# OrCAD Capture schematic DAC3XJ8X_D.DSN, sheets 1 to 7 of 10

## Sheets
1 SHEET 1 - BLOCK DIAGRAM: title: BLOCK DIAGRAM; rev: D; note: DAC3XJ8X EVM
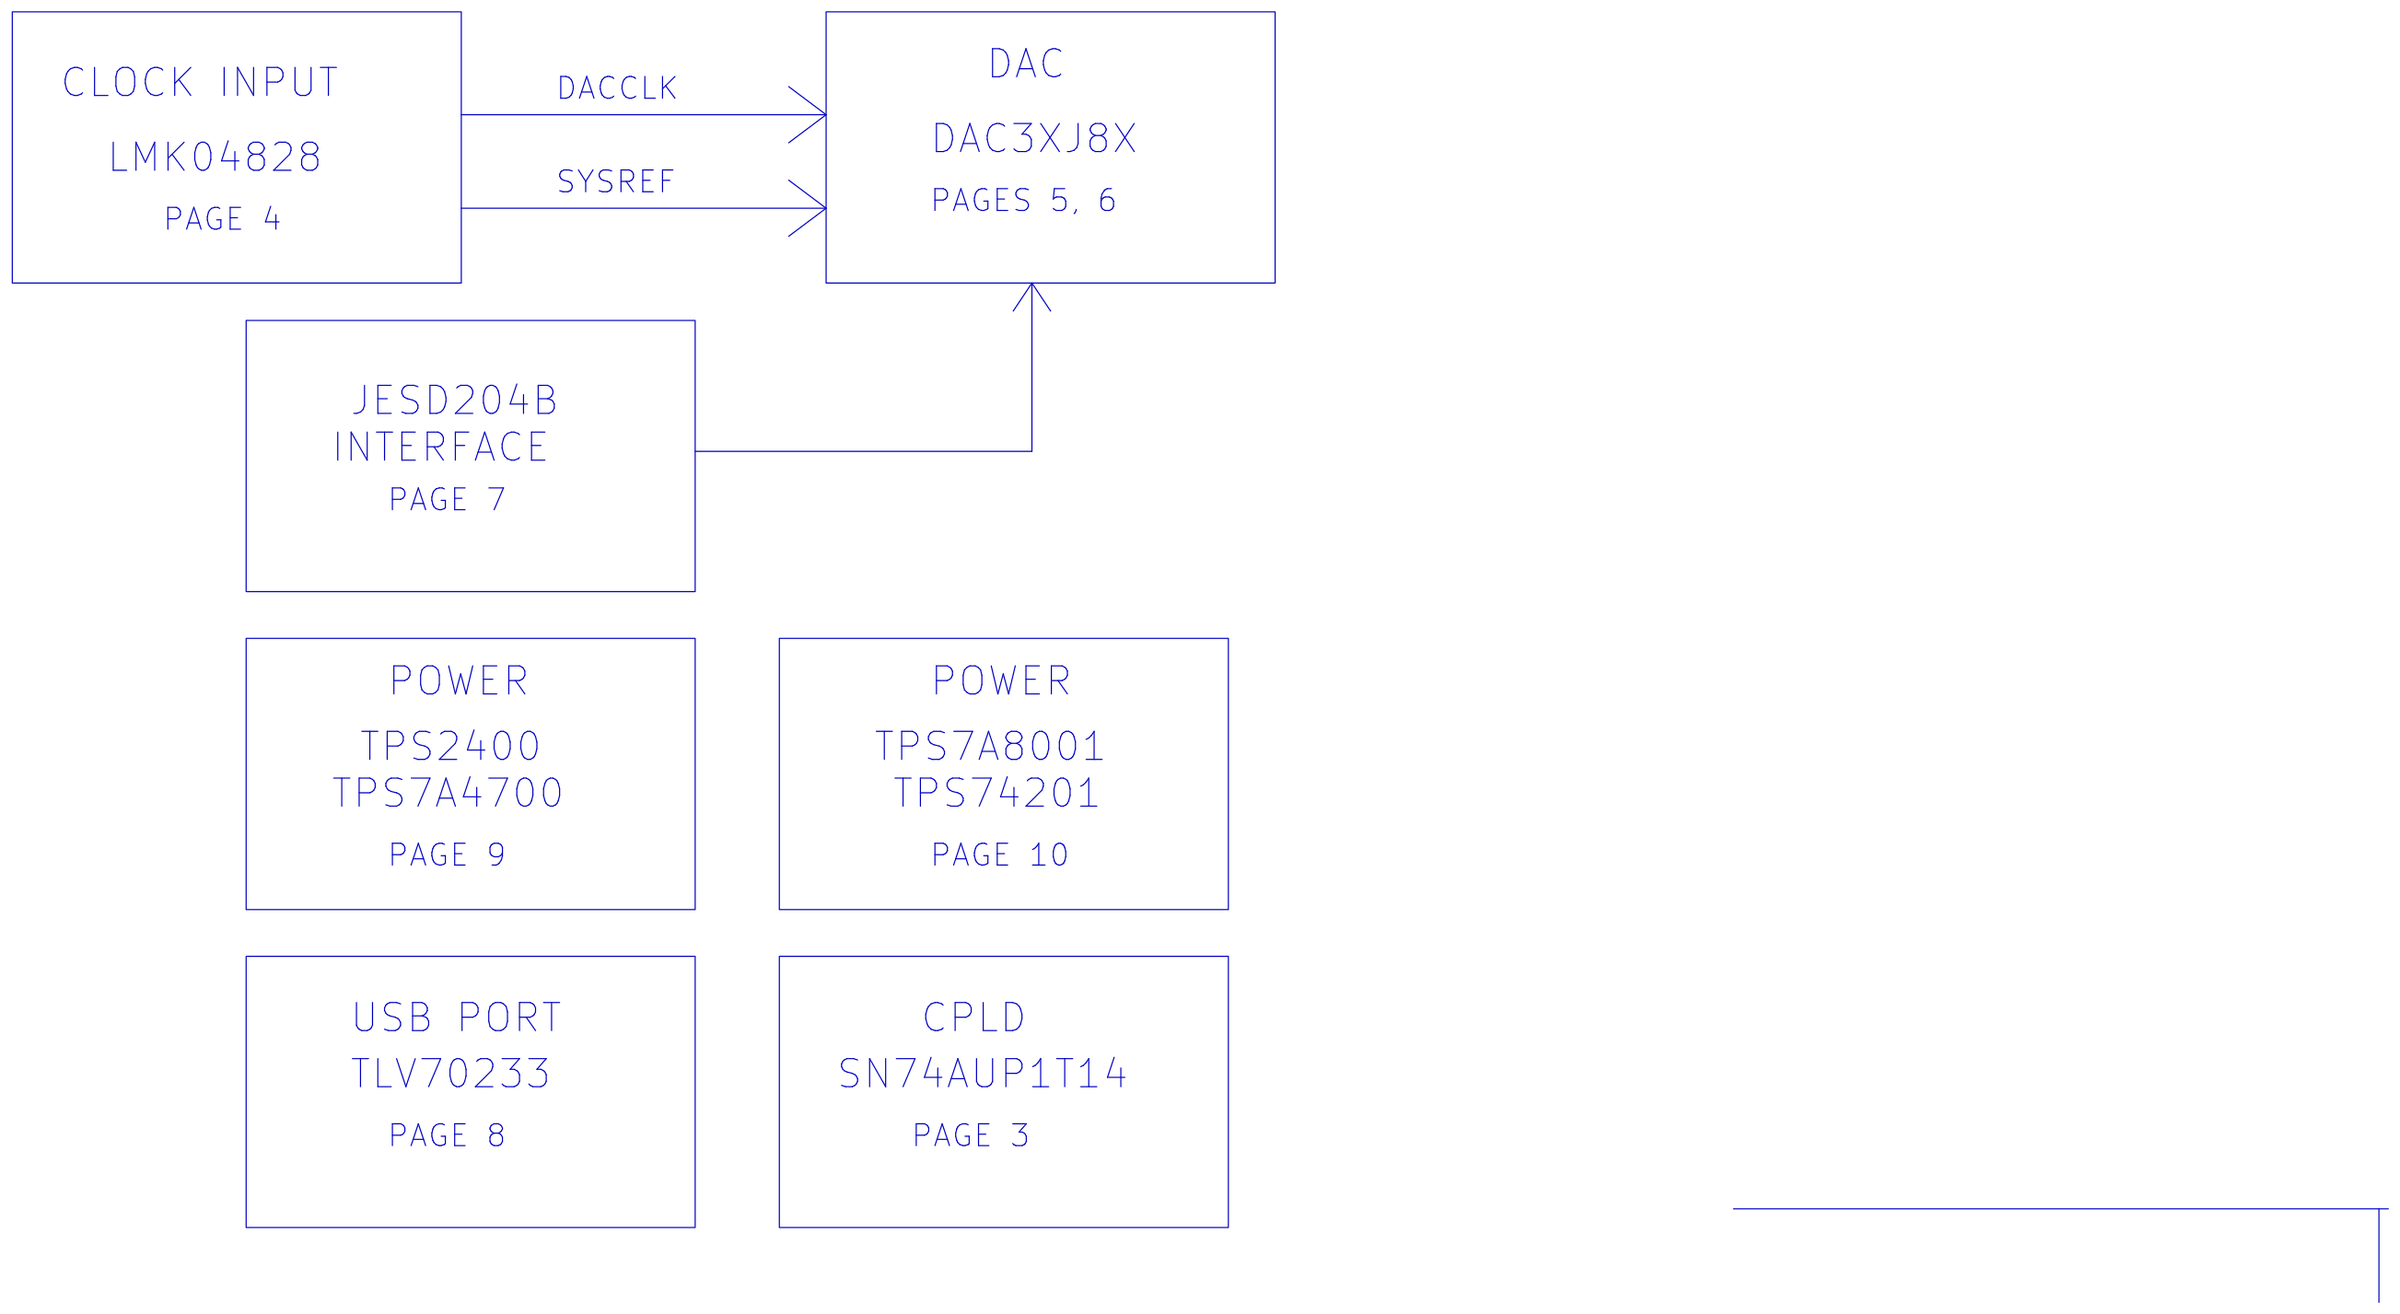
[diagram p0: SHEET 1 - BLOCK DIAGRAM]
2 SHEET 10 - MORE POWER: size B; title: MAIN POWER
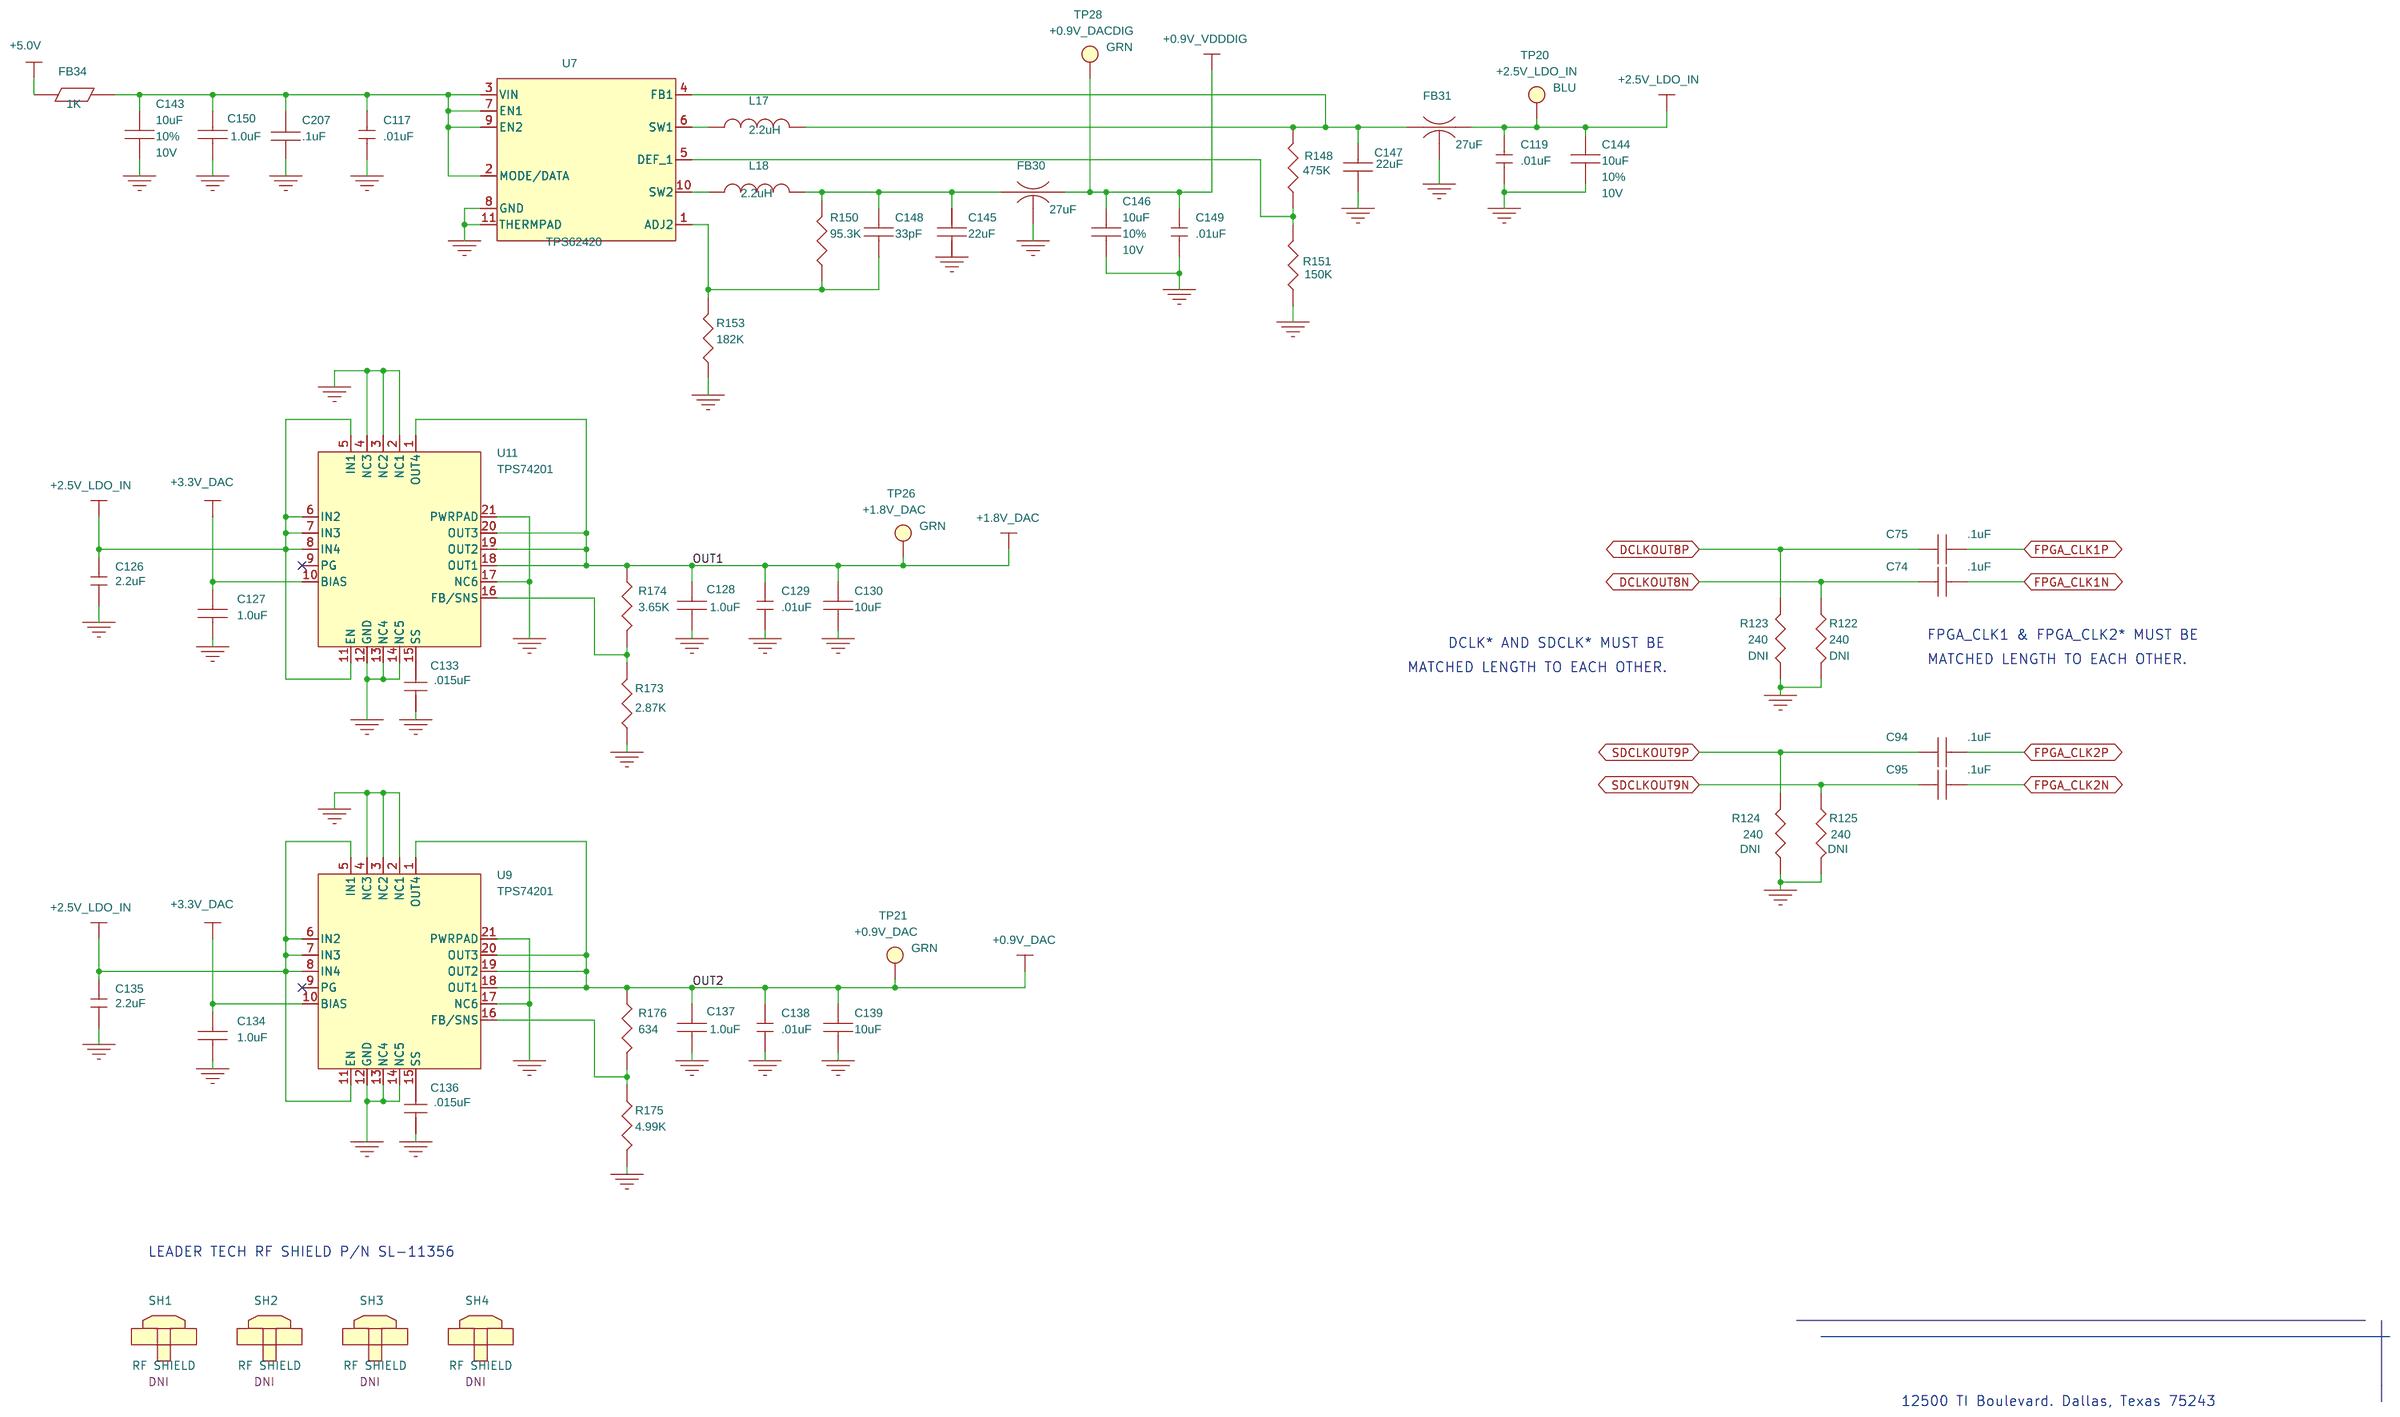
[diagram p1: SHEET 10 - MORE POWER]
3 SHEET 6 - POWER FOR DAC: size B; title: DAC
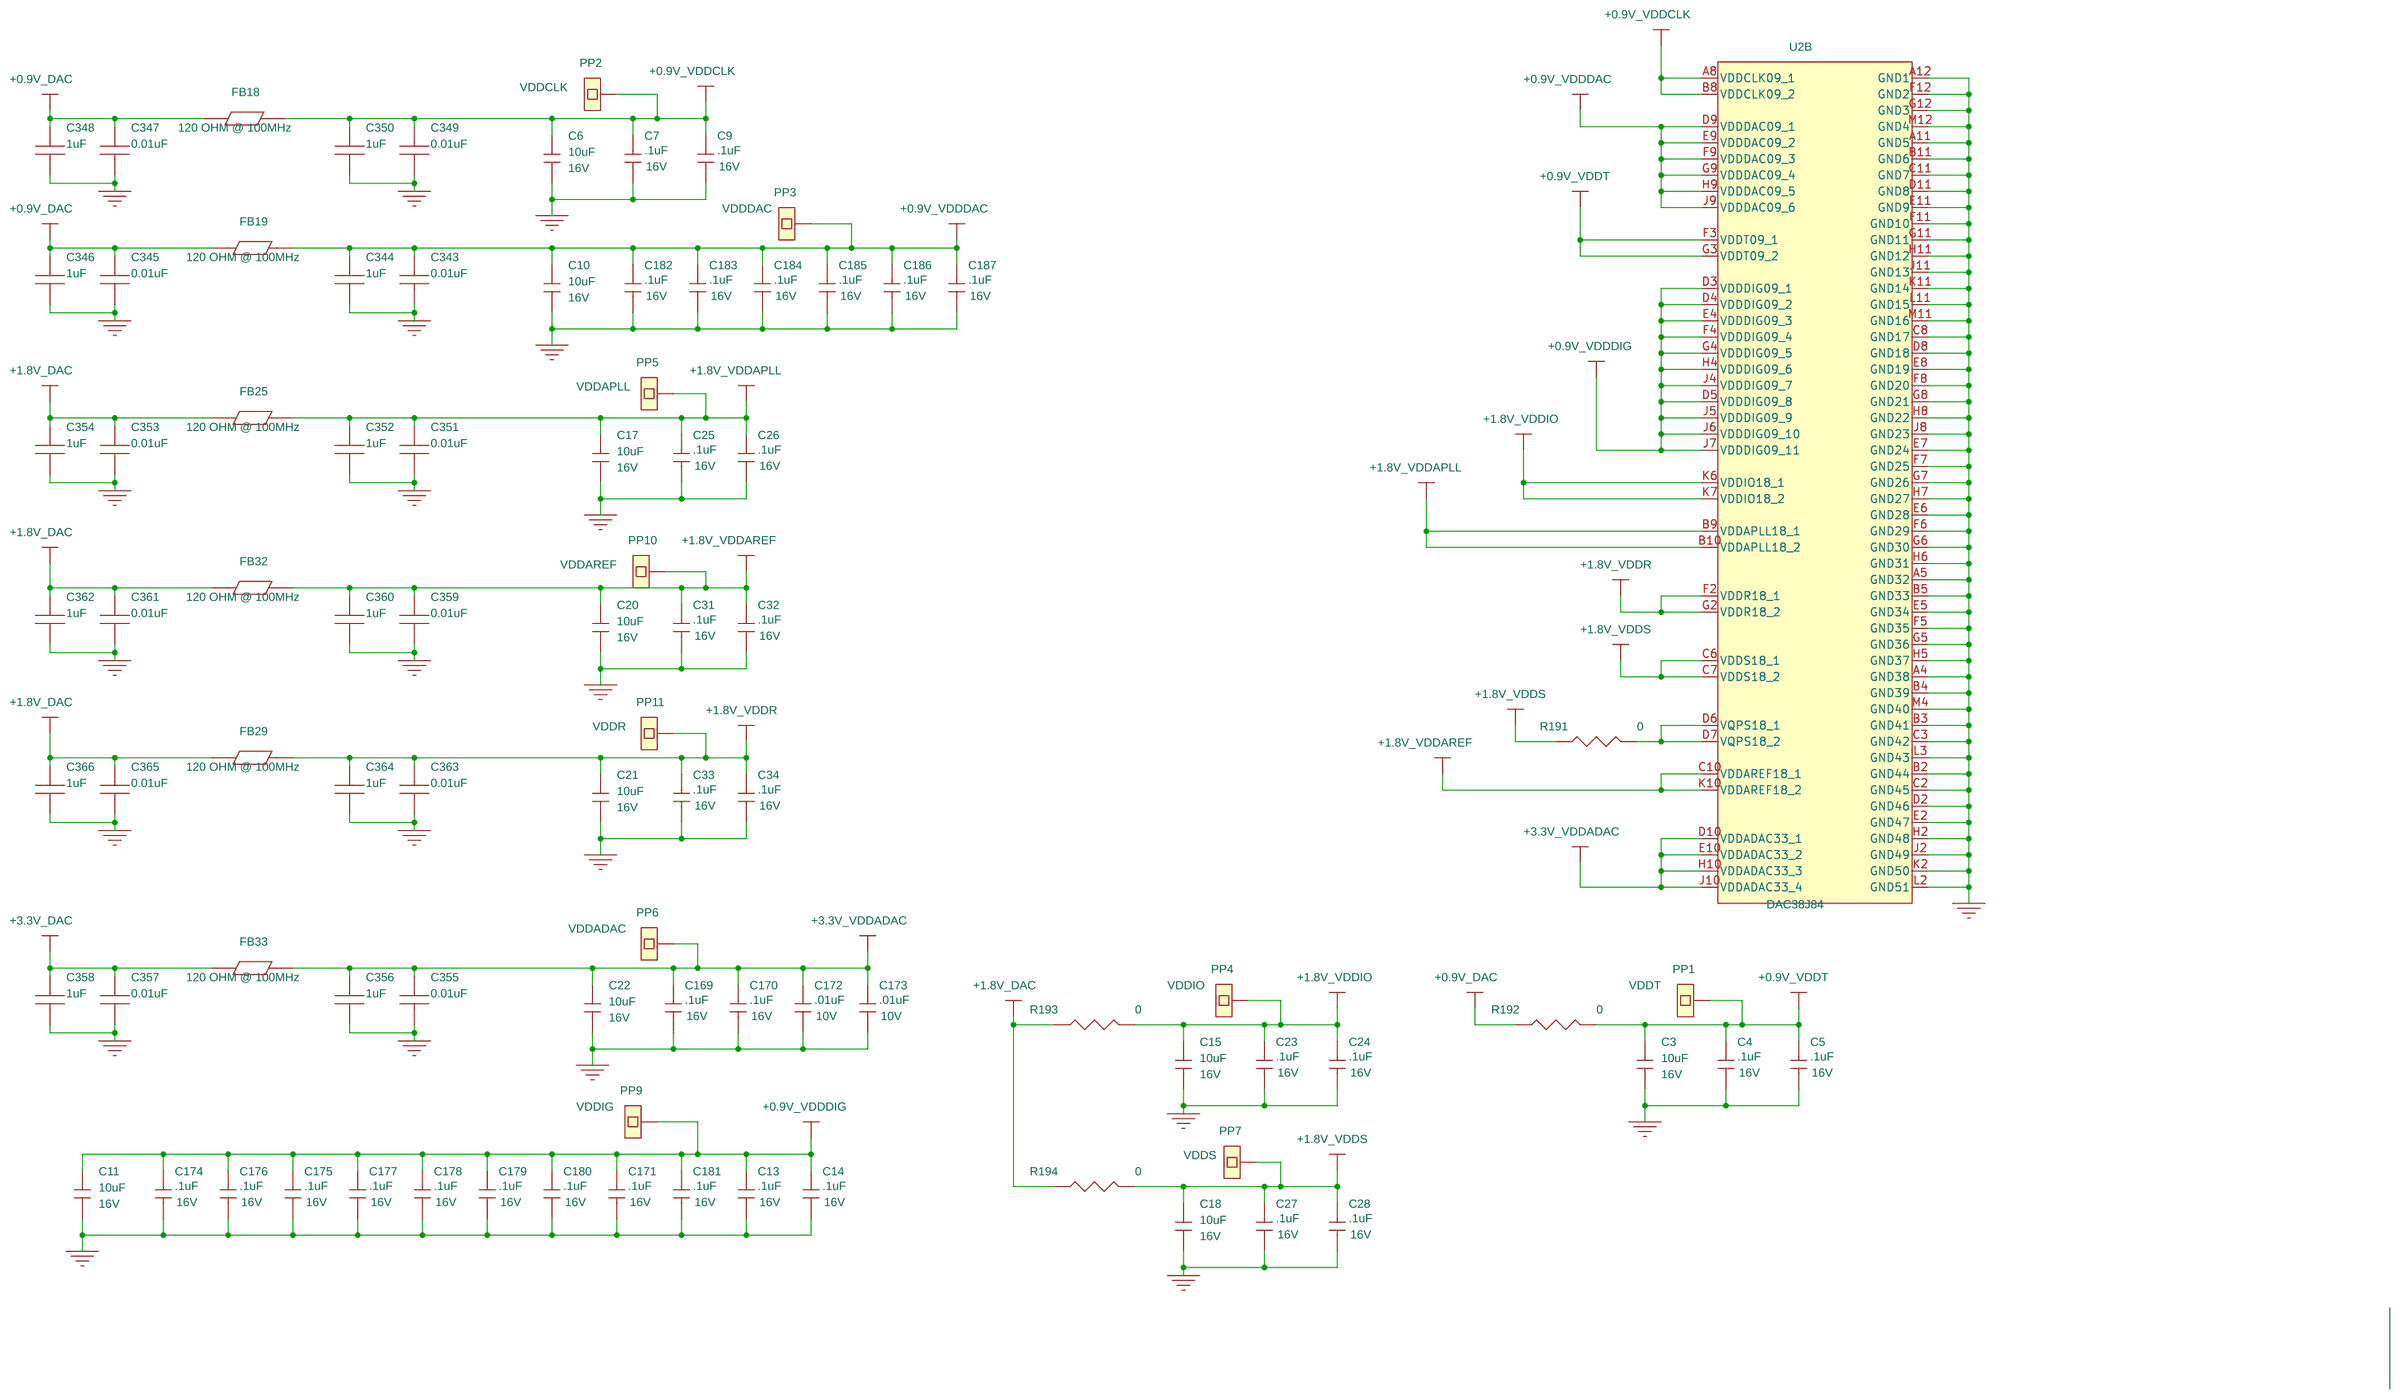
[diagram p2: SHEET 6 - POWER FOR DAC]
4 SHEET 2 - TRNSFRMR  2 DAC: size B; title: DAC
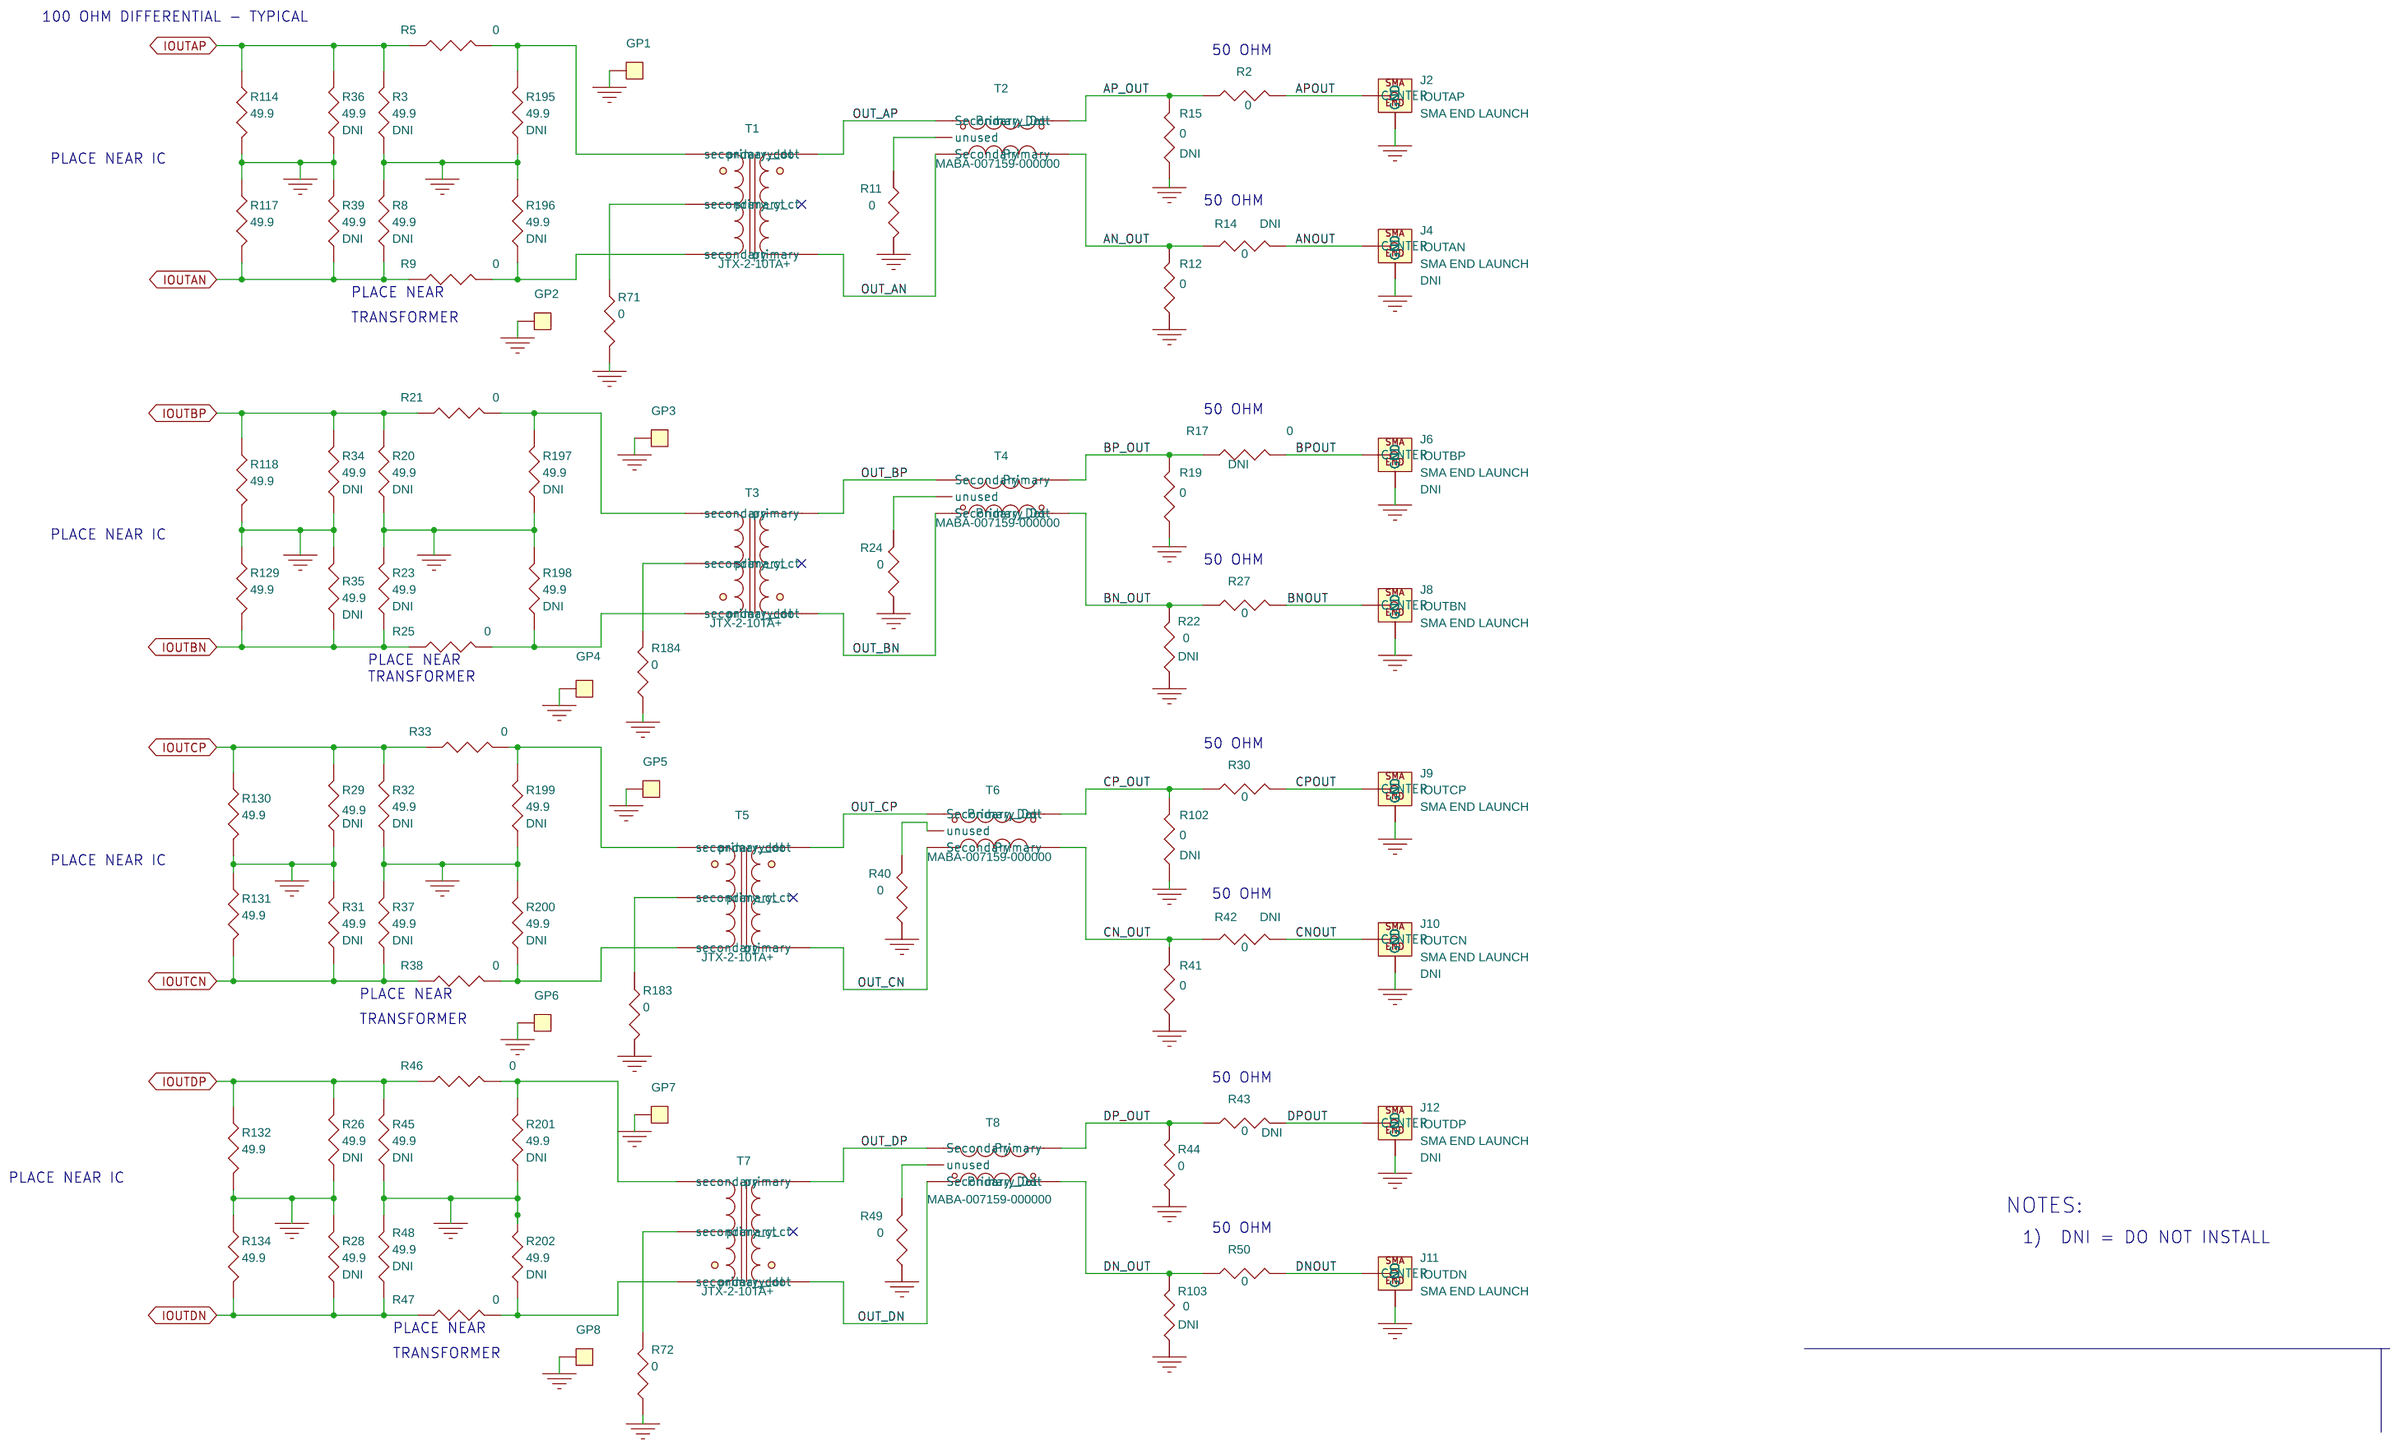
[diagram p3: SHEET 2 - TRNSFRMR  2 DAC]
5 SHEET 3 - CPLD: size B; title: CPLD
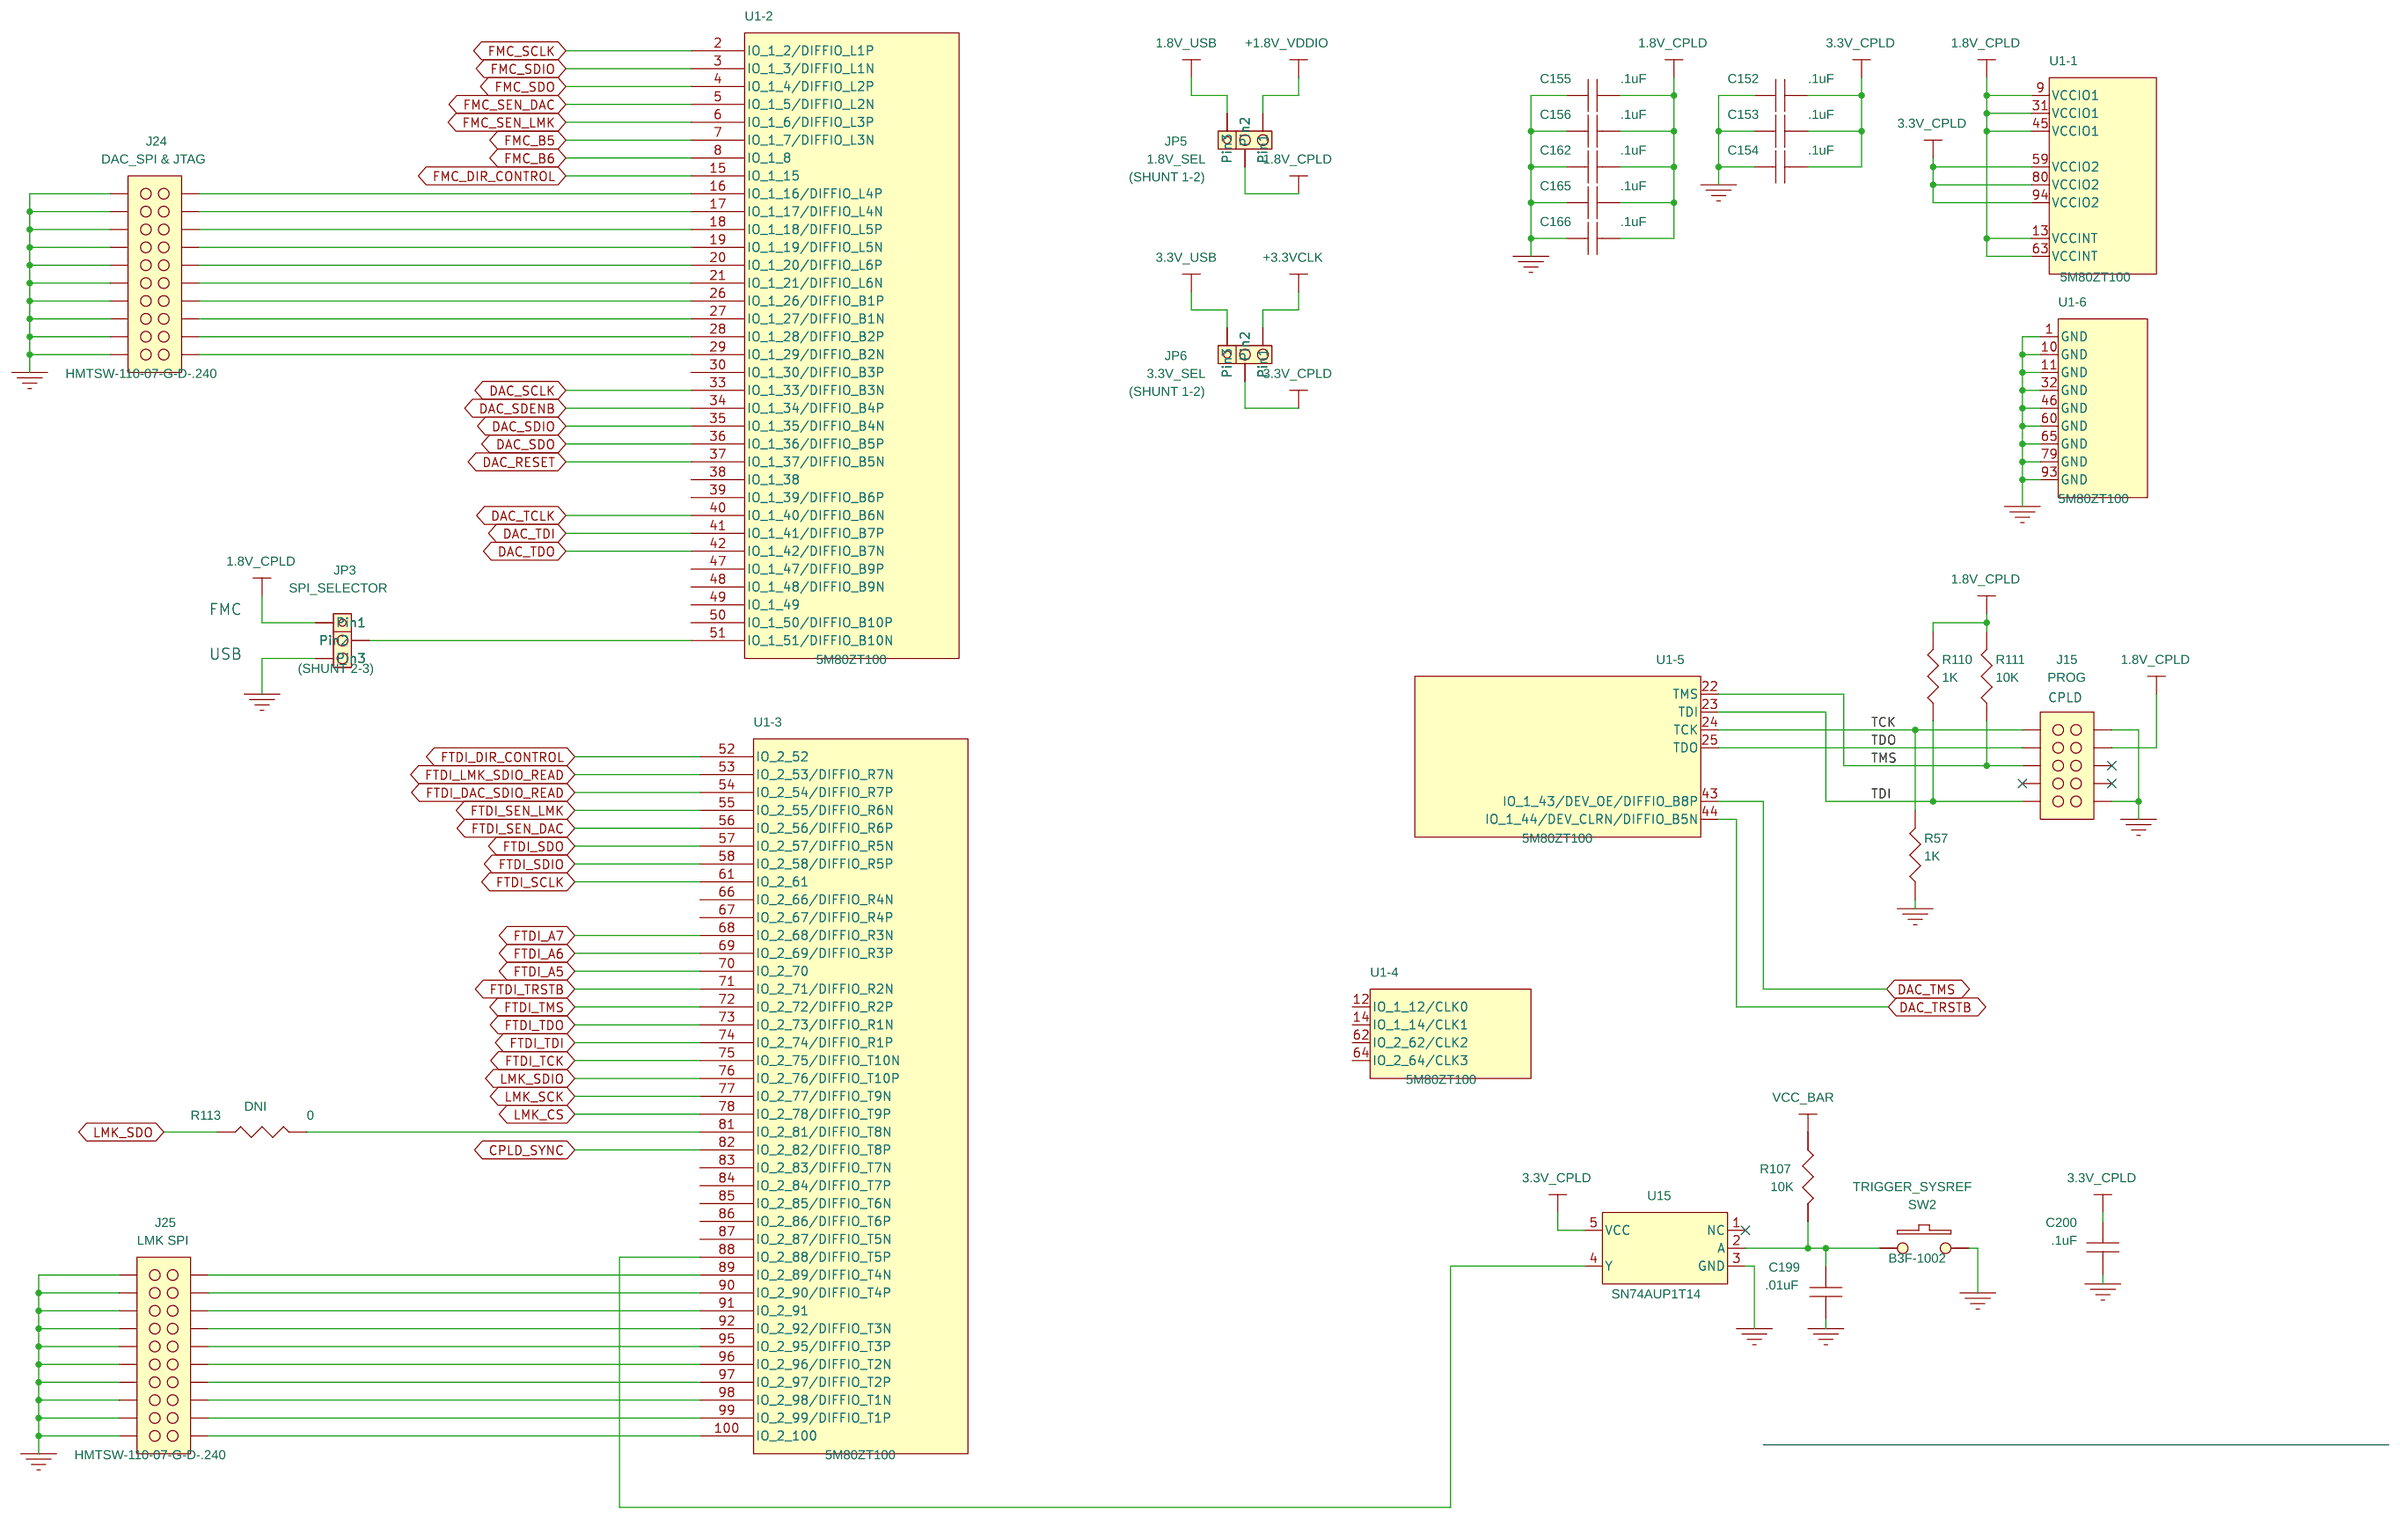
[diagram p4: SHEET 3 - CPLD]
6 SHEET 4 - LMK: size B; title: CLOCK
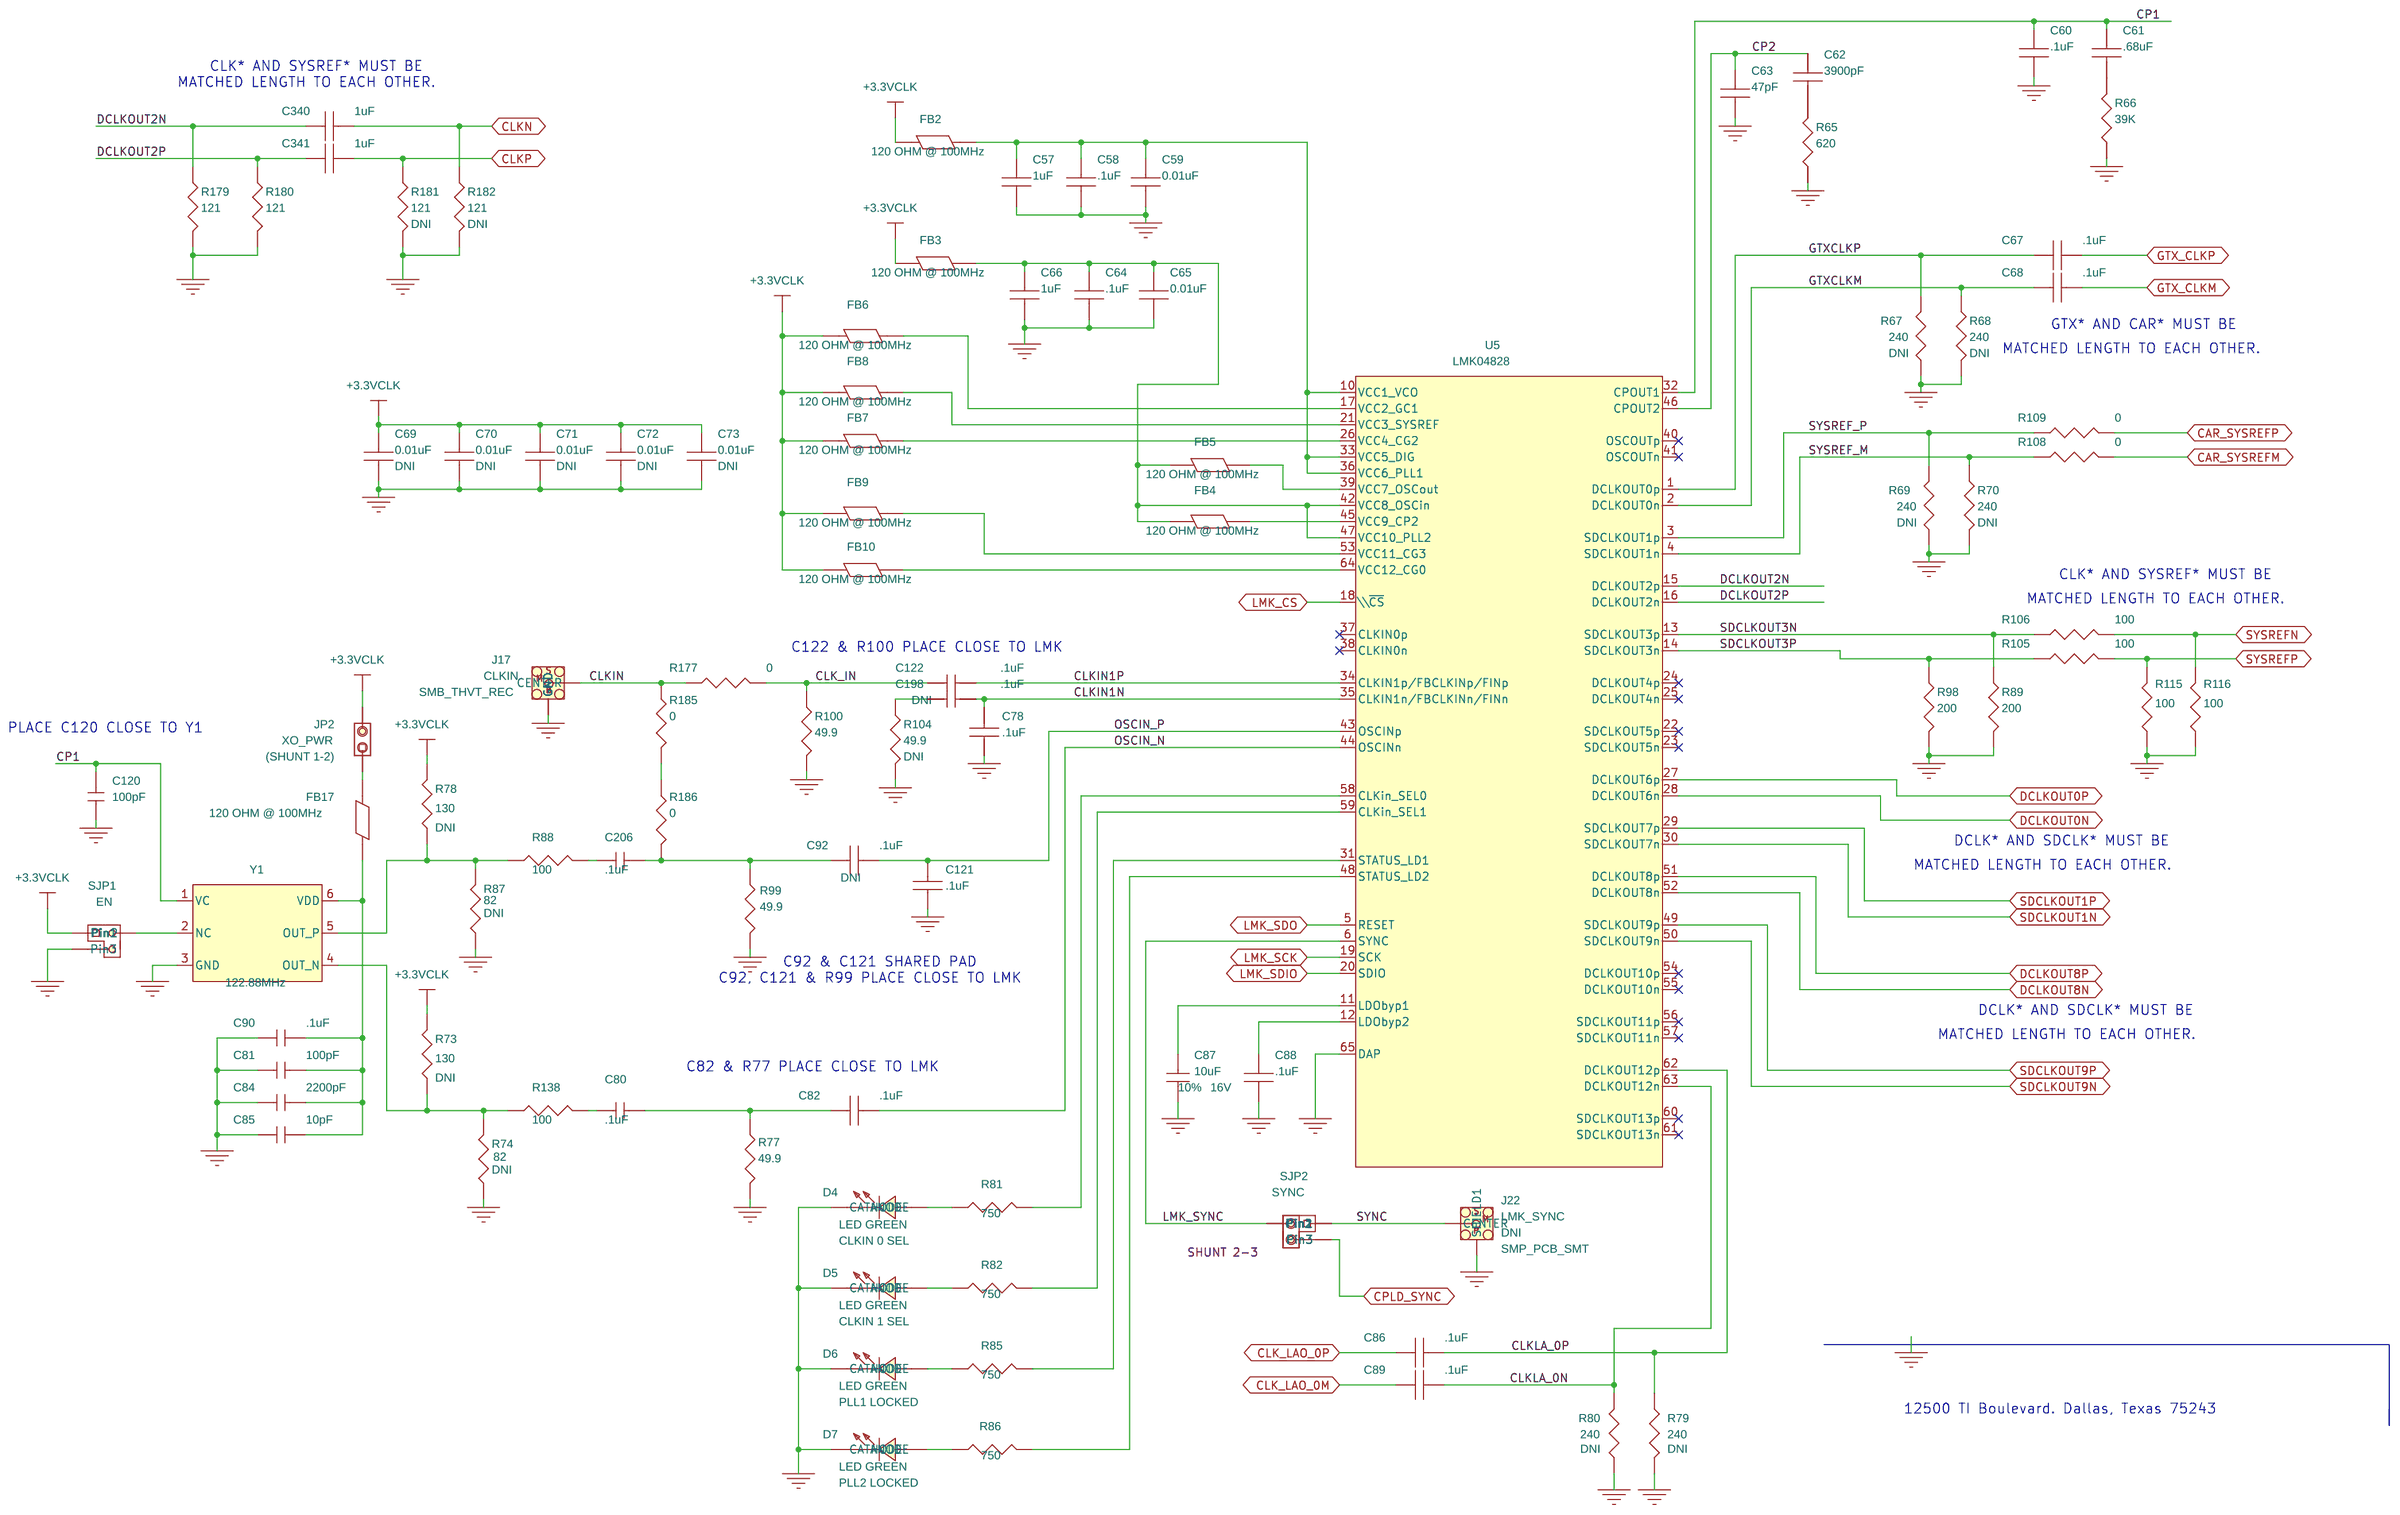
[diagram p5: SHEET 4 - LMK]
7 SHEET 5 - DAC: size B; title: DAC
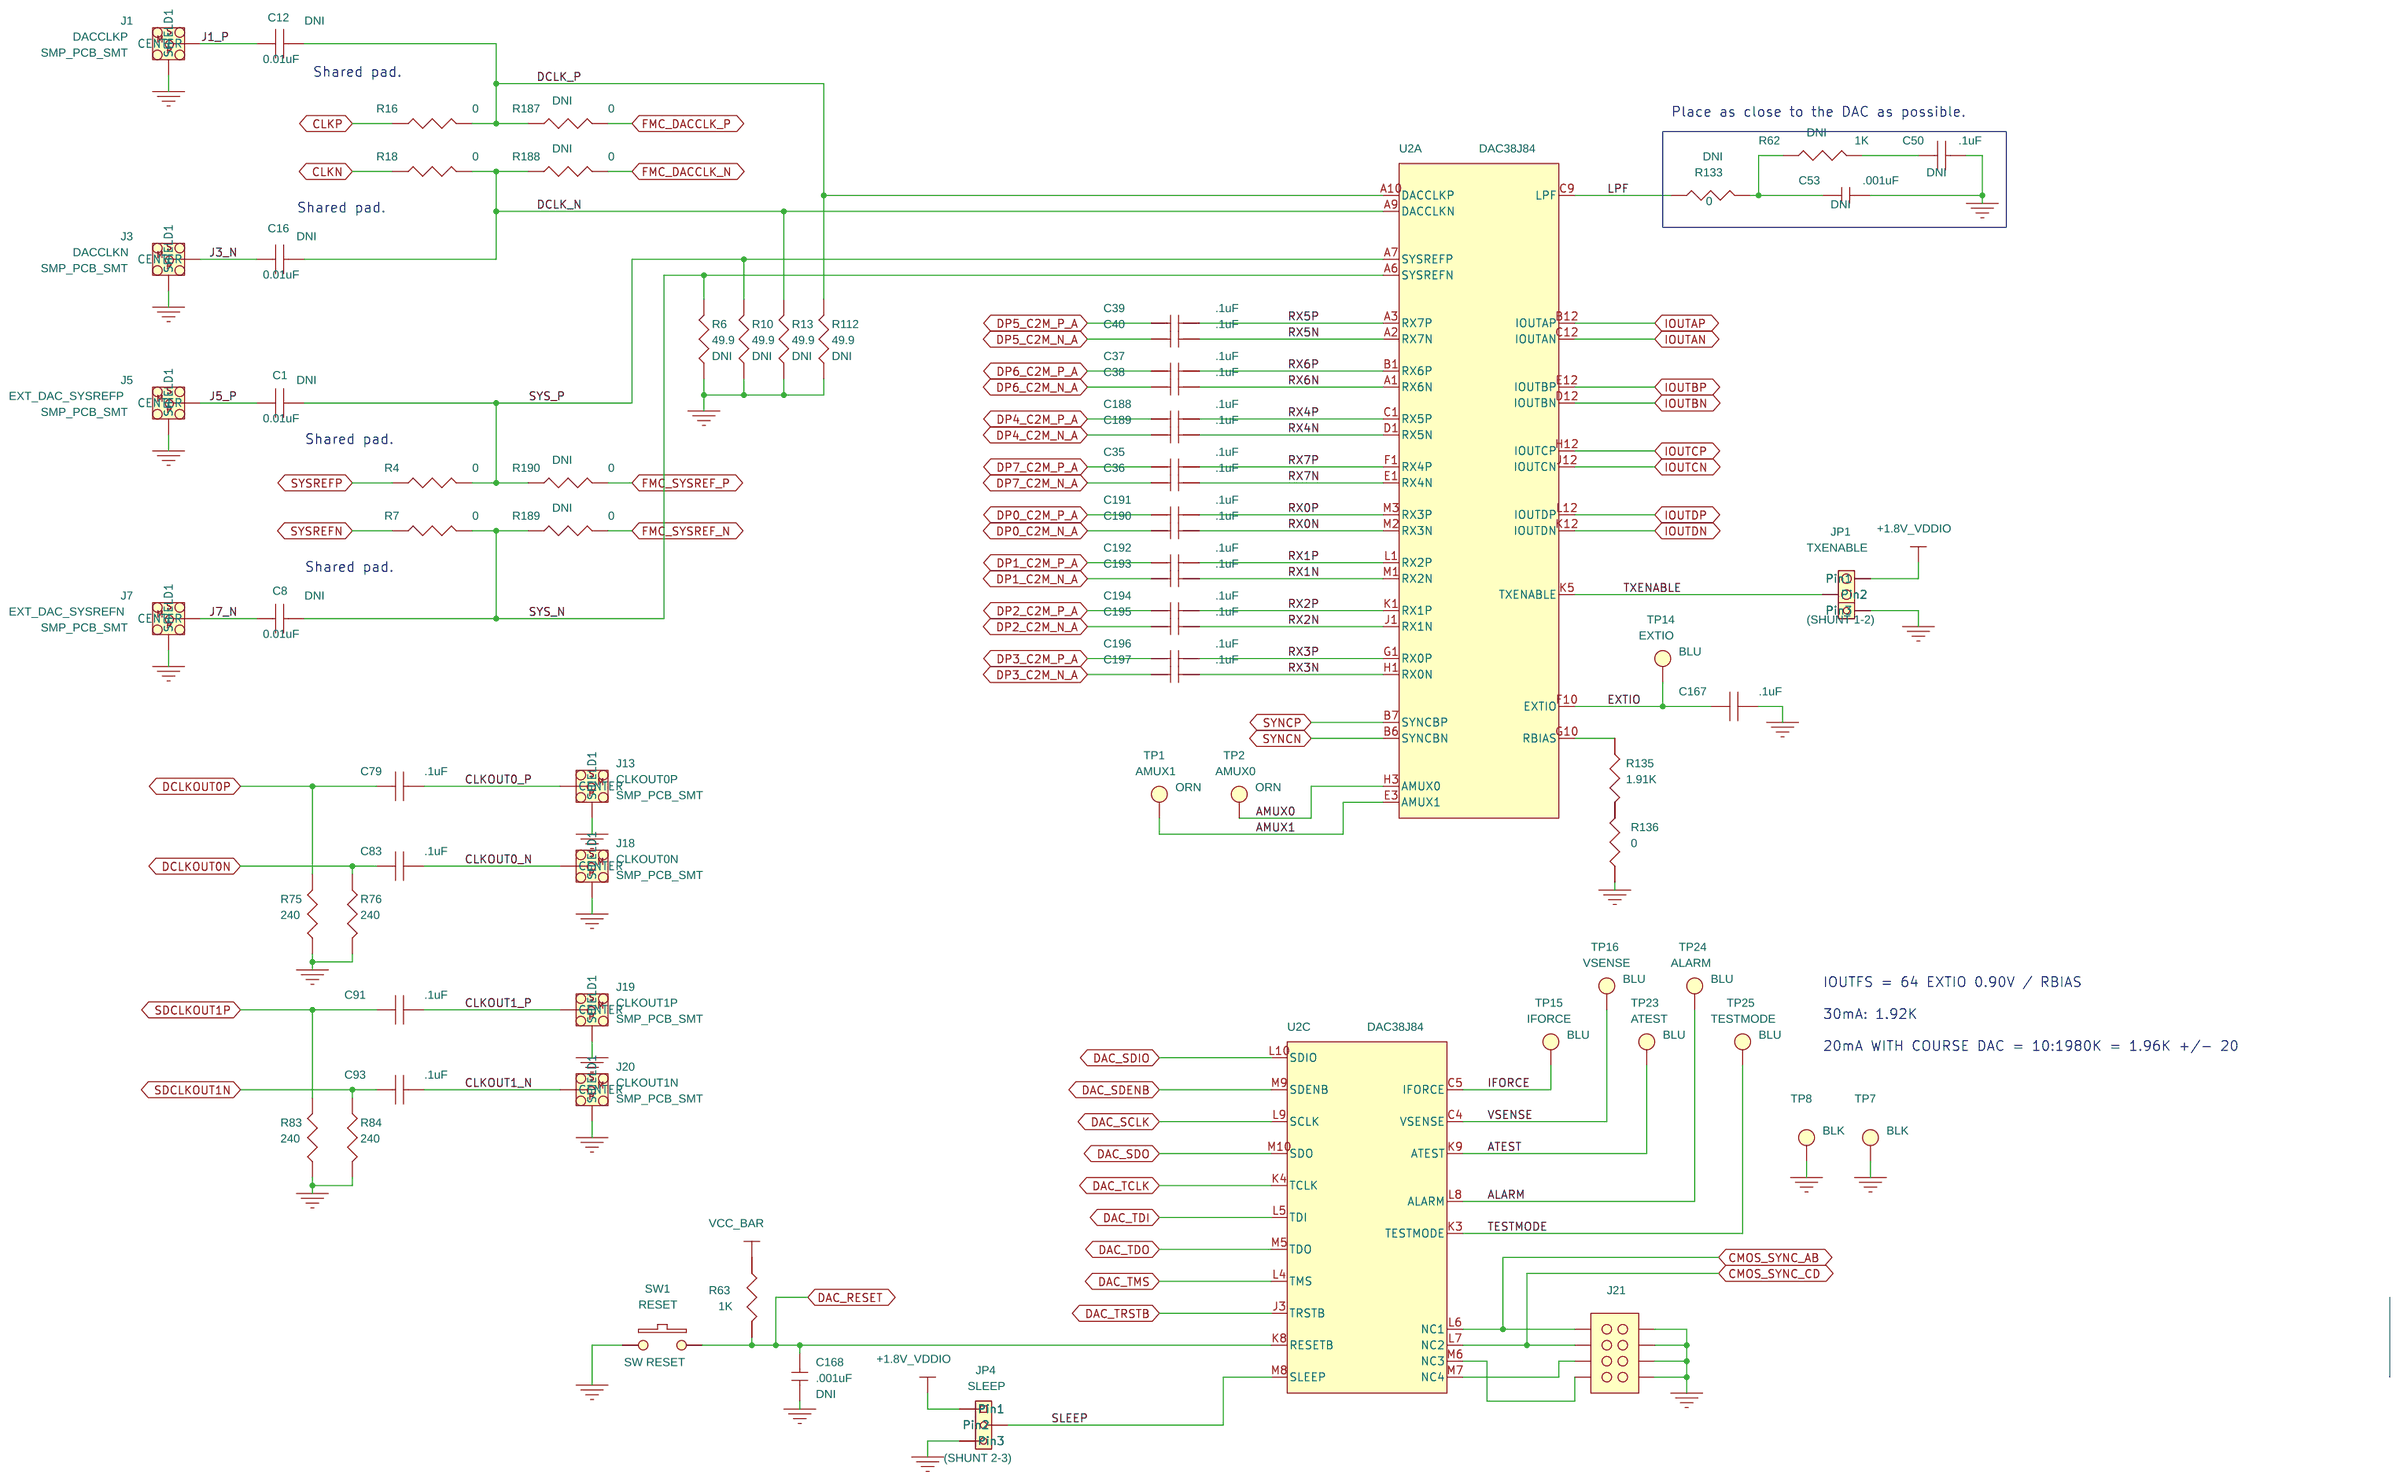
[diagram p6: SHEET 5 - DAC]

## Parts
sheet SHEET 2 - TRNSFRMR  2 DAC
GP1  GND PAD  [testpad20_30]
GP2  GND PAD  [testpad20_30]
GP3  GND PAD  [testpad20_30]
GP4  GND PAD  [testpad20_30]
GP5  GND PAD  [testpad20_30]
GP6  GND PAD  [testpad20_30]
GP7  GND PAD  [testpad20_30]
GP8  GND PAD  [testpad20_30]
J2  SMA END LAUNCH  [SMA_SMEL_DUAL_PSF-S01_250x215]
J4  SMA END LAUNCH  [SMA_SMEL_DUAL_PSF-S01_250x215]
J6  SMA END LAUNCH  [SMA_SMEL_DUAL_PSF-S01_250x215]
J8  SMA END LAUNCH  [SMA_SMEL_DUAL_PSF-S01_250x215]
J9  SMA END LAUNCH  [SMA_SMEL_DUAL_PSF-S01_250x215]
J10  SMA END LAUNCH  [SMA_SMEL_DUAL_PSF-S01_250x215]
J11  SMA END LAUNCH  [SMA_SMEL_DUAL_PSF-S01_250x215]
J12  SMA END LAUNCH  [SMA_SMEL_DUAL_PSF-S01_250x215]
R2  0  [0402]
R3  49.9  [0402]
R5  0  [0402]
R8  49.9  [0402]
R9  0  [0402]
R11  0  [0402]
R12  0  [0402]
R14  0  [0402]
R15  0  [0402]
R17  0  [0402]
R19  0  [0402]
R20  49.9  [0402]
R21  0  [0402]
R22  0  [0402]
R23  49.9  [0402]
R24  0  [0402]
R25  0  [0402]
R26  49.9  [0402]
R27  0  [0402]
R28  49.9  [0402]
R29  49.9  [0402]
R30  0  [0402]
R31  49.9  [0402]
R32  49.9  [0402]
R33  0  [0402]
R34  49.9  [0402]
R35  49.9  [0402]
R36  49.9  [0402]
R37  49.9  [0402]
R38  0  [0402]
R39  49.9  [0402]
R40  0  [0402]
R41  0  [0402]
R42  0  [0402]
R43  0  [0402]
R44  0  [0402]
R45  49.9  [0402]
R46  0  [0402]
R47  0  [0402]
R48  49.9  [0402]
R49  0  [0402]
R50  0  [0402]
R71  0  [0402]
R72  0  [0402]
R102  0  [0402]
R103  0  [0402]
R114  49.9  [0201]
R117  49.9  [0201]
R118  49.9  [0201]
R129  49.9  [0201]
R130  49.9  [0201]
R131  49.9  [0201]
R132  49.9  [0201]
R134  49.9  [0201]
R183  0  [0402]
R184  0  [0402]
R195  49.9  [0402]
R196  49.9  [0402]
R197  49.9  [0402]
R198  49.9  [0402]
R199  49.9  [0402]
R200  49.9  [0402]
R201  49.9  [0402]
R202  49.9  [0402]
T1  JTX-2-10TA+  [TFMR_6_RF_DUAL_FOOTPRINT]
T2  MABA-007159-000000  [TFMR_6_RF_DUAL_FOOTPRINT]
T3  JTX-2-10TA+  [TFMR_6_RF_DUAL_FOOTPRINT]
T4  MABA-007159-000000  [TFMR_6_RF_DUAL_FOOTPRINT]
T5  JTX-2-10TA+  [TFMR_6_RF_DUAL_FOOTPRINT]
T6  MABA-007159-000000  [TFMR_6_RF_DUAL_FOOTPRINT]
T7  JTX-2-10TA+  [TFMR_6_RF_DUAL_FOOTPRINT]
T8  MABA-007159-000000  [TFMR_6_RF_DUAL_FOOTPRINT]
sheet SHEET 3 - CPLD
C152  .1uF  [0402]
C153  .1uF  [0402]
C154  .1uF  [0402]
C155  .1uF  [0402]
C156  .1uF  [0402]
C162  .1uF  [0402]
C165  .1uF  [0402]
C166  .1uF  [0402]
C199  .01uF  [0603]
C200  .1uF  [0402]
J15  HTSW-105-07-G-D  [HDR_THVT_2x5_100_M]
J24  HMTSW-110-07-G-D-.240  [HDR_THVT_2x10_100_M]
J25  HMTSW-110-07-G-D-.240  [HDR_THVT_2x10_100_M]
JP3  Jumper_1x3_100_430L  [HDR_THVT_1x3_100_M]
JP5  Jumper_1x3_100_430L  [HDR_THVT_1x3_100_M]
JP6  Jumper_1x3_100_430L  [HDR_THVT_1x3_100_M]
R57  1K  [0402]
R107  10K  [0402]
R110  1K  [0402]
R111  10K  [0402]
R113  0  [0402]
SW2  B3F-1002  [SW_THVT_SPST_4_B3F]
U1  5M80ZT100  [tqfp_100_551x551_20]  (sections -1,-2,-3,-4,-5,-6)
U15  SN74AUP1T14  [SOP_5_85X55_26]
Z_SH-H4  SHUNT-HEADER
Z_SH-H5  SHUNT-HEADER
Z_SH-H6  SHUNT-HEADER
sheet SHEET 4 - LMK
C57  1uF  [0402]
C58  .1uF  [0402]
C59  0.01uF  [0402]
C60  .1uF  [0402]
C61  .68uF  [0402]
C62  3900pF  [0402]
C63  47pF  [0402]
C64  .1uF  [0402]
C65  0.01uF  [0402]
C66  1uF  [0402]
C67  .1uF  [0402]
C68  .1uF  [0402]
C69  0.01uF  [0402]
C70  0.01uF  [0402]
C71  0.01uF  [0402]
C72  0.01uF  [0402]
C73  0.01uF  [0402]
C78  .1uF  [0402]
C80  .1uF  [0402]
C81  100pF  [0603]
C82  .1uF  [0402]
C84  2200pF  [0402]
C85  10pF  [0402]
C86  .1uF  [0402]
C87  10uF  [0603]
C88  .1uF  [0402]
C89  .1uF  [0402]
C90  .1uF  [0402]
C92  .1uF  [0402]
C120  100pF  [0603]
C121  .1uF  [0402]
C122  .1uF  [0402]
C198  .1uF  [0402]
C206  .1uF  [0402]
C340  1uF  [0402]
C341  1uF  [0402]
D4  LED GREEN  [LED_1206]
D5  LED GREEN  [LED_1206]
D6  LED GREEN  [LED_1206]
D7  LED GREEN  [LED_1206]
FB2  120 OHM @ 100MHz  [1206]
FB3  120 OHM @ 100MHz  [1206]
FB4  120 OHM @ 100MHz  [1206]
FB5  120 OHM @ 100MHz  [1206]
FB6  120 OHM @ 100MHz  [1206]
FB7  120 OHM @ 100MHz  [1206]
FB8  120 OHM @ 100MHz  [1206]
FB9  120 OHM @ 100MHz  [1206]
FB10  120 OHM @ 100MHz  [1206]
FB17  120 OHM @ 100MHz  [1206]
J17  SMB_THVT_REC  [SMA_THVT_312x312]
J22  SMP_PCB_SMT  [smp_b120]
JP2  HDR, THVT, 2POS  [HDR_THVT_1X2_100_M]
R65  620  [0402]
R66  39K  [0402]
R67  240  [0402]
R68  240  [0402]
R69  240  [0402]
R70  240  [0402]
R73  130  [0603]
R74  82  [0603]
R77  49.9  [0402]
R78  130  [0603]
R79  240  [0402]
R80  240  [0402]
R81  750  [0603]
R82  750  [0603]
R85  750  [0603]
R86  750  [0603]
R87  82  [0603]
R88  100  [0402]
R89  200  [0402]
R98  200  [0402]
R99  49.9  [0402]
R100  49.9  [0402]
R104  49.9  [0402]
R105  100  [0402]
R106  100  [0402]
R108  0  [0402]
R109  0  [0402]
R115  100  [0402]
R116  100  [0402]
R138  100  [0402]
R177  0  [0402]
R179  121  [0402]
R180  121  [0402]
R181  121  [0402]
R182  121  [0402]
R185  0  [0402]
R186  0  [0402]
SJP1  JUMPER_L_0603_SMT  [JUMPER_SMD_L_0603]
SJP2  JUMPER_L_0603_SMT  [JUMPER_SMD_L_0603]
U5  LMK04828  [QFN_64_360X360_0P50MM_PWRPAD]
Y1  122.88MHz  [VCXO_6_CUSTOM]
Z_SH-J7  SHUNT-HEADER
Z_SH-J8  SHUNT-JUMPER-0603
sheet SHEET 5 - DAC
C1  0.01uF  [0402]
C8  0.01uF  [0402]
C12  0.01uF  [0402]
C16  0.01uF  [0402]
C35  .1uF  [0201]
C36  .1uF  [0201]
C37  .1uF  [0201]
C38  .1uF  [0201]
C39  .1uF  [0201]
C40  .1uF  [0201]
C50  .1uF  [0402]
C53  .001uF  [0402]
C79  .1uF  [0402]
C83  .1uF  [0402]
C91  .1uF  [0402]
C93  .1uF  [0402]
C167  .1uF  [0402]
C168  .001uF  [0402]
C188  .1uF  [0201]
C189  .1uF  [0201]
C190  .1uF  [0201]
C191  .1uF  [0201]
C192  .1uF  [0201]
C193  .1uF  [0201]
C194  .1uF  [0201]
C195  .1uF  [0201]
C196  .1uF  [0201]
C197  .1uF  [0201]
J1  SMP_PCB_SMT  [SMP_B120]
J3  SMP_PCB_SMT  [SMP_B120]
J5  SMP_PCB_SMT  [SMP_B120]
J7  SMP_PCB_SMT  [SMP_B120]
J13  SMP_PCB_SMT  [smp_b120]
J18  SMP_PCB_SMT  [smp_b120]
J19  SMP_PCB_SMT  [smp_b120]
J20  SMP_PCB_SMT  [smp_b120]
J21  HMTSW-104-07-G-D-.240  [HDR_THVT_2x4_100_M]
JP1  Jumper_1x3_100_430L  [HDR_THVT_1x3_100_M]
JP4  Jumper_1x3_100_430L  [HDR_THVT_1x3_100_M]
R4  0  [0402]
R6  49.9  [0402]
R7  0  [0402]
R10  49.9  [0402]
R13  49.9  [0402]
R16  0  [0402]
R18  0  [0402]
R62  1K  [0402]
R63  1K  [0402]
R75  240  [0402]
R76  240  [0402]
R83  240  [0402]
R84  240  [0402]
R112  49.9  [0402]
R133  0  [0402]
R135  1.91K  [0402]
R136  0  [0402]
R187  0  [0402]
R188  0  [0402]
R189  0  [0402]
R190  0  [0402]
SW1  SW RESET  [SW_SMVT_RESET]
TP1  ORN  [TP_THVT_100_RND]
TP2  ORN  [TP_THVT_100_RND]
TP7  BLK  [TP_THVT_100_RND_GND]
TP8  BLK  [TP_THVT_100_RND_GND]
TP14  BLU  [TP_THVT_100_RND]
TP15  BLU  [TP_THVT_100_RND]
TP16  BLU  [TP_THVT_100_RND]
TP23  BLU  [TP_THVT_100_RND]
TP24  BLU  [TP_THVT_100_RND]
TP25  BLU  [TP_THVT_100_RND]
U2  DAC38J84  [BGA_144_10MMx10MM_0P80MM]  (sections A,B,C)
Z_SH-H2  SHUNT-HEADER
Z_SH-H3  SHUNT-HEADER
sheet SHEET 6 - POWER FOR DAC
C3  10uF  [0603]
C4  .1uF  [0201]
C5  .1uF  [0201]
C6  10uF  [0603]
C7  .1uF  [0201]
C9  .1uF  [0201]
C10  10uF  [0603]
C11  10uF  [0603]
C13  .1uF  [0201]
C14  .1uF  [0201]
C15  10uF  [0603]
C17  10uF  [0603]
C18  10uF  [0603]
C20  10uF  [0603]
C21  10uF  [0603]
C22  10uF  [0603]
C23  .1uF  [0201]
C24  .1uF  [0201]
C25  .1uF  [0201]
C26  .1uF  [0201]
C27  .1uF  [0201]
C28  .1uF  [0201]
C31  .1uF  [0201]
C32  .1uF  [0201]
C33  .1uF  [0201]
C34  .1uF  [0201]
C169  .1uF  [0201]
C170  .1uF  [0201]
C171  .1uF  [0201]
C172  .01uF  [0201]
C173  .01uF  [0201]
C174  .1uF  [0201]
C175  .1uF  [0201]
C176  .1uF  [0201]
C177  .1uF  [0201]
C178  .1uF  [0201]
C179  .1uF  [0201]
C180  .1uF  [0201]
C181  .1uF  [0201]
C182  .1uF  [0201]
C183  .1uF  [0201]
C184  .1uF  [0201]
C185  .1uF  [0201]
C186  .1uF  [0201]
C187  .1uF  [0201]
C343  0.01uF  [0402]
C344  1uF  [0402]
C345  0.01uF  [0402]
C346  1uF  [0402]
C347  0.01uF  [0402]
C348  1uF  [0402]
C349  0.01uF  [0402]
C350  1uF  [0402]
C351  0.01uF  [0402]
C352  1uF  [0402]
C353  0.01uF  [0402]
C354  1uF  [0402]
C355  0.01uF  [0402]
C356  1uF  [0402]
C357  0.01uF  [0402]
C358  1uF  [0402]
C359  0.01uF  [0402]
C360  1uF  [0402]
C361  0.01uF  [0402]
C362  1uF  [0402]
C363  0.01uF  [0402]
C364  1uF  [0402]
C365  0.01uF  [0402]
C366  1uF  [0402]
FB18  120 OHM @ 100MHz  [IND_0402]
FB19  120 OHM @ 100MHz  [IND_0402]
FB25  120 OHM @ 100MHz  [IND_0402]
FB29  120 OHM @ 100MHz  [IND_0402]
FB32  120 OHM @ 100MHz  [IND_0402]
FB33  120 OHM @ 100MHz  [IND_0402]
PP1  PROBE POINT  [PROBE_POINT_22PAD]
PP2  PROBE POINT  [PROBE_POINT_22PAD]
PP3  PROBE POINT  [PROBE_POINT_22PAD]
PP4  PROBE POINT  [PROBE_POINT_22PAD]
PP5  PROBE POINT  [PROBE_POINT_22PAD]
PP6  PROBE POINT  [PROBE_POINT_22PAD]
PP7  PROBE POINT  [PROBE_POINT_22PAD]
PP9  PROBE POINT  [PROBE_POINT_22PAD]
PP10  PROBE POINT  [PROBE_POINT_22PAD]
PP11  PROBE POINT  [PROBE_POINT_22PAD]
R191  0  [0402]
R192  0  [0402]
R193  0  [0402]
R194  0  [0402]
sheet SHEET 10 - MORE POWER
C74  .1uF  [0402]
C75  .1uF  [0402]
C94  .1uF  [0402]
C95  .1uF  [0402]
C117  .01uF  [0603]
C119  .01uF  [0603]
C126  2.2uF  [0603]
C127  1.0uF  [0603]
C128  1.0uF  [0603]
C129  .01uF  [0603]
C130  10uF  [0805]
C133  .015uF  [0402]
C134  1.0uF  [0603]
C135  2.2uF  [0603]
C136  .015uF  [0402]
C137  1.0uF  [0603]
C138  .01uF  [0603]
C139  10uF  [0805]
C143  10uF  [0805]
C144  10uF  [0805]
C145  22uF  [1206]
C146  10uF  [0805]
C147  22uF  [1206]
C148  33pF  [0402]
C149  .01uF  [0603]
C150  1.0uF  [0603]
C207  .1uF  [0402]
FB30  27uF  [1206_BEAD_NFM31P]
FB31  27uF  [1206_BEAD_NFM31P]
FB34  1K  [1810]
L17  2.2uH  [LPS3015]
L18  2.2uH  [LPS3015]
R122  240  [0402]
R123  240  [0402]
R124  240  [0402]
R125  240  [0402]
R148  475K  [0402]
R150  95.3K  [0402]
R151  150K  [0402]
R153  182K  [0402]
R173  2.87K  [0603]
R174  3.65K  [0603]
R175  4.99K  [0603]
R176  634  [0603]
SH1  RF SHIELD
SH2  RF SHIELD
SH3  RF SHIELD
SH4  RF SHIELD
TP20  BLU  [TP_THVT_100_RND]
TP21  GRN  [TP_THVT_100_RND]
TP26  GRN  [TP_THVT_100_RND]
TP28  GRN  [TP_THVT_100_RND]
U7  TPS62420  [SON_DRC_10]
U9  TPS74201  [qfn20_rgw_p65pitch]
U11  TPS74201  [qfn20_rgw_p65pitch]

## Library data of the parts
GP1-GP8 = TEST_POINT_0: Mfr_Name: NO PART; Mfr_Part_Number: CU PAD ONLY; Note: DNI
J2 = SMA-END_JACK_142-0761-801_ROUND: Mfr_Name: Johnson Components; Mfr_Part_Number: 142-0711-821; TI_Silktext: IOUTAP
J4 = SMA-END_JACK_142-0761-801_ROUND: Mfr_Name: Johnson Components; Mfr_Part_Number: 142-0711-821_DNI; Note: DNI; TI_Silktext: IOUTAN
J6 = SMA-END_JACK_142-0761-801_ROUND: Mfr_Name: Johnson Components; Mfr_Part_Number: 142-0711-821_DNI; Note: DNI; TI_Silktext: IOUTBP
J8 = SMA-END_JACK_142-0761-801_ROUND: Mfr_Name: Johnson Components; Mfr_Part_Number: 142-0711-821; TI_Silktext: IOUTBN
J9 = SMA-END_JACK_142-0761-801_ROUND: Mfr_Name: Johnson Components; Mfr_Part_Number: 142-0711-821; TI_Silktext: IOUTCP
J10 = SMA-END_JACK_142-0761-801_ROUND: Mfr_Name: Johnson Components; Mfr_Part_Number: 142-0711-821_DNI; Note: DNI; TI_Silktext: IOUTCN
J11 = SMA-END_JACK_142-0761-801_ROUND: Mfr_Name: Johnson Components; Mfr_Part_Number: 142-0711-821; TI_Silktext: IOUTDN
J12 = SMA-END_JACK_142-0761-801_ROUND: Mfr_Name: Johnson Components; Mfr_Part_Number: 142-0711-821_DNI; Note: DNI; TI_Silktext: IOUTDP
R2 R4 R5 R7 R9 R11 R12 R16 R18 R19 R21 R24 R25 R27 R30 R33 R38 R40 R41 R44 R46 R47 R49 R50 R71 R72 R183 R184 = R: Mfr_Name: PANASONIC; Mfr_Part_Number: ERJ-2GE0R00X; TOL: 5%
R3 R6 R8 R10 R13 R20 R23 R32 R37 R112 R195-R200 = R: Mfr_Name: PANASONIC; Mfr_Part_Number: ERJ-2RKF49R9X_DNI; Note: DNI; TOL: 1%
R14 R15 R17 R22 R42 R43 R102 R103 R113 R133 R187-R190 = R: Mfr_Name: PANASONIC; Mfr_Part_Number: ERJ-2GE0R00X_DNI; Note: DNI; TOL: 5%
R26 R28 R29 R31 R34-R36 R39 = Res_0402_49.9_H: Mfr_Part_Number: ERJ-2RKF49R9X_DNI; Note: DNI; TOL: 1%
R45 R48 R201 R202 = R: Mfr_Name: PANASONIC; Mfr_Part_Number: ERJ-2RKF49R9X_DNI; NOTE: DNI; TOL: 1%
R114 R117 R118 R129-R132 R134 = Res_0201_49.9
T1 T3 T5 T7 = ADT4-1T_0
T2 T4 T6 T8 = TFMR_5_ETC1-1-13_4
C58 C64 C67 C68 C74 C75 C78 C79 C83 C86 C88 C89 C91 C93-C95 C121 C152-C156 C162 C165-C167 C207 = CAPACITOR_NP_1: Mfr_Name: MURATA; Mfr_Part_Number: GRM155R71C104KA88D; TOL: 10%; Voltage: 16V
C199 = CAP_NP_0: Mfr_Name: AVX; Mfr_Part_Number: 06035C103JAT2A; TOL: 5%; VOLTAGE: 50V
C60 C82 C200 = CAP_NP_0: Mfr_Name: MURATA; Mfr_Part_Number: GRM155R71C104KA88D; TOL: 10%
J15 = HEADER_2x5_100: TI_SILKTEXT: PROG
J24 = HEADER_2x10_100: TI_SILKTEXT: DAC_SPI & JTAG
J25 = HEADER_2x10_100: TI_SILKTEXT: LMK SPI
JP3 = Jumper_1x3_100_0: Mfr_Name: SAMTEC; Mfr_Part_Number: HMTSW-103-07-G-S-.230; Note: (SHUNT 2-3); TI_Silktext: SPI_SELECTOR
JP5 = Jumper_1x3_100_0: Mfr_Name: SAMTEC; Mfr_Part_Number: HMTSW-103-07-G-S-.230; Note: (SHUNT 1-2); TI_Silktext: 1.8V_SEL
JP6 = Jumper_1x3_100_0: Mfr_Name: SAMTEC; Mfr_Part_Number: HMTSW-103-07-G-S-.230; Note: (SHUNT 1-2); TI_Silktext: 3.3V_SEL
R57 = R_0: Mfr_Name: PANASONIC; Mfr_Part_Number: ERJ-2RKF1001X; TOL: 1%
R107 = R_1: CLASS: DISCRETE; Mfr_Name: PANASONIC; Mfr_Part_Number: ERJ-2RKF1002X; TOL: 1%
R110 = R_0: Mfr_Name: PANASONIC; Mfr_Part_Number: ERJ-2RKF1001X; PART_NUMBER: Panasonic ERJ-2RKF1001X; TOL: 1%
R111 = R_0: CLASS: DISCRETE; Mfr_Name: PANASONIC; Mfr_Part_Number: ERJ-2RKF1002X; TOL: 1%
SW2 = SW_SMVT_SPST_4_BF3: TI_SILK: TRIGGER_SYSREF; TI_SILKTEXT: <TI_SILKTEXT>
U1 = ALTERA_5M80ZT100
U15 = SN74AUP1T14DCKR: Mfr_Name: TI
Z_SH-H2-Z_SH-H6 = SHUNT-HEADER: Mfr_Name: TE CONNECTIVITY; Mfr_Part_Number: 382811-8
C57 C66 C340 C341 C344 C346 C348 C350 C352 C354 C356 C358 C360 C362 C364 C366 = CAPACITOR_NP_1: Mfr_Name: MURATA; Mfr_Part_Number: GRM155R61A105KE15D; TOL: 10%; Voltage: 16V
C59 C65 C343 C345 C347 C349 C351 C353 C355 C357 C359 C361 C363 C365 = CAPACITOR_NP_1: Mfr_Name: MURATA; Mfr_Part_Number: GRM155R71H103KA88D; TOL: 10%; Voltage: 16V
C61 = CAP_NP_0: Mfr_Name: MURATA; Mfr_Part_Number: GRM155F50J684ZE01D; TOL: 10%
C62 = CAP_NP_0: Mfr_Name: MURATA; Mfr_Part_Number: GRM155R71H392KA01D; TOL: 5%; VOLTAGE: 50V
C63 = CAP_NP_0: Mfr_Name: MURATA; Mfr_Part_Number: GRM1555C1H470JA01D; TOL: 10%; VOLTAGE: 16V
C69-C73 = CAPACITOR_NP_1: Mfr_Name: MURATA; Mfr_Part_Number: GRM155R71H103KA88D_DNI; Note: DNI; TOL: 10%; Voltage: 16V
C80 C90 C122 C206 = CAP_0402_0.1uF_H: Mfr_Part_Number: GRM155R71C104KA88D; TOL: 10%; Voltage: 16V
C81 C120 = CAP_0603_100pF_H
C84 = CAP_0402_2200pF_H: Mfr_Name: MURATA; Mfr_Part_Number: GRM155R71E222KA01D
C85 = CAP_0402_10pF_H: Mfr_Part_Number: GRM1555C1H100JA01D
C87 = CAP_NP_2: CLASS: DISCRETE; Mfr_Name: TDK; Mfr_Part_Number: C1608X5R1C106M080AB; TOL: 10%; VOLTAGE: 16V
C92 = CAP_NP_0: Mfr_Name: MURATA; Mfr_Part_Number: GRM155R71C104KA88D_DNI; Note: DNI; TOL: 10%
C198 = CAP_0402_0.1uF_H: Mfr_Part_Number: GRM155R71C104KA88D_DNI; Note: DNI; TOL: 10%; Voltage: 16V
D4 = LED: Mfr_Name: LITE ON; Mfr_Part_Number: LTST-C150KGKT; TI_Silktext: CLKIN 0 SEL
D5 = LED: Mfr_Name: LITE ON; Mfr_Part_Number: LTST-C150KGKT; TI_Silktext: CLKIN 1 SEL
D6 = LED: Mfr_Name: LITE ON; Mfr_Part_Number: LTST-C150KGKT; TI_Silktext: PLL1 LOCKED
D7 = LED: Mfr_Name: LITE ON; Mfr_Part_Number: LTST-C150KGKT; TI_Silktext: PLL2 LOCKED
FB2-FB10 FB17 = FERRITE_BEAD_0402_H: Isat: 500mA; Mfr_Name: MURATA; Mfr_Part_Number: BLM31PG121SN1L
J17 = SMA-THVT_142-0701-201_REC: TI_Silktext: CLKIN
J22 = SMP_PLUG_SMT: Mfr_Name: MOLEX INC.; Mfr_Part_Number: 0853050232_DNI; Note: DNI; TI_Silktext: LMK_SYNC
JP2 = SMD_JUMPER_1x2: Mfr_Name: SAMTEC; Mfr_Part_Number: HTSW-102-08-G-S; Note: (SHUNT 1-2); TI_Silktext: XO_PWR
R65 = R_1: CLASS: DISCRETE; Mfr_Name: PANASONIC; Mfr_Part_Number: ERJ-2GEJ621X; TOL: 1%
R66 = R_1: CLASS: DISCRETE; Mfr_Name: PANASONIC; Mfr_Part_Number: ERJ-2GEJ393X; TOL: 1%
R67-R70 R79 R80 R122-R125 = Res_0402_249: Mfr_Part_Number: ERJ-2RKF2400X_DNI; Note: DNI
R73 R78 = RESISTOR: CLASS: DISCRETE; Mfr_Name: DALE; Mfr_Part_Number: CRCW0603130RFKEA_DNI; Note: DNI; TOL: 1%; Wattage: 1/10W
R74 R87 = RESISTOR: CLASS: DISCRETE; Mfr_Name: DALE; Mfr_Part_Number: CRCW060382R0FKEA_DNI; Note: DNI; TOL: 1%; Wattage: 1/10W
R77 R100 = Res_0402_49.9: TOL: 1%
R81 R82 R85 R86 = RESISTOR: CLASS: DISCRETE; Mfr_Name: DALE; Mfr_Part_Number: CRCW0603750RFKEA
R88 R115 R116 R138 = Res_0402_100_H
R89 R98 = Res_0402_249: Mfr_Part_Number: ERJ-2RKF2000X
R99 = Res_0402_49.9: Mfr_Part_Number: ERJ-2RKF49R9X; TOL: 1%
R104 = Res_0402_49.9: Mfr_Part_Number: ERJ-2RKF49R9X_DNI; Note: DNI; TOL: 1%
R105 R106 = Res_0402_Zero_H: Mfr_Part_Number: ERJ-2RKF1000X
R108 R109 R177 R191-R194 = Res_0402_Zero_H
R179 R180 = Res_0402_121
R181 R182 = Res_0402_121: Mfr_Part_Number: ERJ-2RKF1210X_DNI; Note: DNI
R185 R186 = Res_0402_Zero_DNI
SJP1 = JUMPER_SMD_L_0603: TI_Silktext: EN
SJP2 = JUMPER_SMD_L_0603: TI_Silktext: SYNC
U5 = LMK04828_0: Mfr_Name: TI; Mfr_Part_Number: LMK04828BISQ/NOPB
Y1 = OSC_SM_6_TCO-2100-SERIES_2: Mfr_Name: Crystek; Mfr_Part_Number: CVHD-950-122.88
Z_SH-J7 = SHUNT-JUMPER: Mfr_Name: TE CONNECTIVITY; Mfr_Part_Number: 382811-8; Note: SHUNT FOR HEADER; TI_SILK: SHUNT 1-2
Z_SH-J8 = SHUNT-JUMPER-0603: TI_SILK: SHUNT 2-3
C1 C8 C12 C16 = CAP_NP_1: Mfr_Name: MURATA; Mfr_Part_Number: GRM155R71H103KA88D_DNI; Note: DNI; TOL: 10%; VOLTAGE: 25V
C4 C5 C7 C9 C13 C14 C23-C28 C31-C40 C169-C171 C174-C197 = CAP0402: Mfr_Name: MURATA; Mfr_Part_Number: GRM033R61A104KE15D; TOL: 10%; Voltage: 16V
C50 = CAPACITOR_NP_1: Mfr_Name: MURATA; Mfr_Part_Number: GRM155R71C104KA88D_DNI; Note: DNI; TOL: 10%; Voltage: 16V
C53 C168 = CAP_0402_0.001uF_H: Mfr_Part_Number: 04025C102JAT2A_DNI; Note: DNI
J1 = SMP_PLUG_SMT: Mfr_Name: MOLEX INC.; Mfr_Part_Number: 0853050232; TI_Silktext: DACCLKP
J3 = SMP_PLUG_SMT: Mfr_Name: MOLEX INC.; Mfr_Part_Number: 0853050232; TI_Silktext: DACCLKN
J5 = SMP_PLUG_SMT: Mfr_Name: MOLEX INC.; Mfr_Part_Number: 0853050232; TI_Silktext: EXT_DAC_SYSREFP
J7 = SMP_PLUG_SMT: Mfr_Name: MOLEX INC.; Mfr_Part_Number: 0853050232; TI_Silktext: EXT_DAC_SYSREFN
J13 = SMP_PLUG_SMT: Mfr_Name: MOLEX INC.; Mfr_Part_Number: 0853050232; TI_Silktext: CLKOUT0P
J18 = SMP_PLUG_SMT: Mfr_Name: MOLEX INC.; Mfr_Part_Number: 0853050232; TI_Silktext: CLKOUT0N
J19 = SMP_PLUG_SMT: Mfr_Name: MOLEX INC.; Mfr_Part_Number: 0853050232; TI_Silktext: CLKOUT1P
J20 = SMP_PLUG_SMT: Mfr_Name: MOLEX INC.; Mfr_Part_Number: 0853050232; TI_Silktext: CLKOUT1N
J21 = HEADER_2x4_100
JP1 = Jumper_1x3_100_0: Mfr_Name: SAMTEC; Mfr_Part_Number: HMTSW-103-07-G-S-.230; Note: (SHUNT 1-2); TI_Silktext: TXENABLE
JP4 = Jumper_1x3_100_0: Mfr_Name: SAMTEC; Mfr_Part_Number: HMTSW-103-07-G-S-.230; Note: (SHUNT 2-3); TI_Silktext: SLEEP
R62 = R_0: Mfr_Name: PANASONIC; Mfr_Part_Number: ERJ-2RKF1001X_DNI; Note: DNI; TOL: 1%
R63 = R_0: Mfr_Name: Panasonic; Mfr_Part_Number: ERJ-2RKF1001X; PART_NUMBER: Panasonic ERJ-2RKF1001X; TOL: 1%
R75 R76 R83 R84 = Res_0402_249: Mfr_Part_Number: ERJ-2RKF2400X
R135 = Res_0402_1.8K: Mfr_Part_Number: ERJ-2RKF1911X
R136 = Res_0402_10_H: Mfr_Part_Number: ERJ-2GE0R00X
SW1 = SPST_PB_KT11P3JM_5: Mfr_Name: C&K; Mfr_Part_Number: KT11P3JM34LFS; TI_SILKTEXT: RESET
TP1 = TESTPOINT_ORANGE: TI_SILKTEXT: AMUX1
TP2 = TESTPOINT_ORANGE: TI_SILKTEXT: AMUX0
TP7 TP8 = TESTPOINT_BLK
TP14 = TESTPOINT_BLUE: TI_SILKTEXT: EXTIO
TP15 = TESTPOINT_BLUE: TI_SILKTEXT: IFORCE
TP16 = TESTPOINT_BLUE: TI_SILKTEXT: VSENSE
TP23 = TESTPOINT_BLUE: TI_SILKTEXT: ATEST
TP24 = TESTPOINT_BLUE: TI_SILKTEXT: ALARM
TP25 = TESTPOINT_BLUE: TI_SILKTEXT: TESTMODE
U2 = DAC38J84_144PIN: Mfr_Part_Number: DAC38J84IAAV
C3 C6 C10 C11 C15 C17 C18 C20-C22 = CAP0201: CLASS: DISCRETE; Mfr_Name: TDK CORP; Mfr_Part_Number: C1608X5R1C106M080AB; TOL: 20%; VOLTAGE: 16V
C172 C173 = CAP0402: Mfr_Name: TDK; Mfr_Part_Number: C0603X5R1A103K030BA; TOL: +/-10%; Voltage: 10V
FB18 FB19 FB25 FB29 FB32 FB33 = FERRITE_BEAD_0402_120_H
PP1 = PROBE_POINT_22PAD: TI_Silktext: VDDT
PP2 = PROBE_POINT_22PAD: TI_Silktext: VDDCLK
PP3 = PROBE_POINT_22PAD: TI_Silktext: VDDDAC
PP4 = PROBE_POINT_22PAD: TI_Silktext: VDDIO
PP5 = PROBE_POINT_22PAD: TI_Silktext: VDDAPLL
PP6 = PROBE_POINT_22PAD: TI_Silktext: VDDADAC
PP7 = PROBE_POINT_22PAD: TI_Silktext: VDDS
PP9 = PROBE_POINT_22PAD: TI_Silktext: VDDIG
PP10 = PROBE_POINT_22PAD: TI_Silktext: VDDAREF
PP11 = PROBE_POINT_22PAD: TI_Silktext: VDDR
C117 C119 C129 C138 C149 = CAP_0603_0.01uF: Mfr_Part_Number: C0603C103K5RACTU
C126 C135 = CAP_0603_2.2uF
C127 C128 C134 C137 C150 = CAP_NP_0: Mfr_Name: YAGEO; Mfr_Part_Number: CC0603KRX7R7BB105; TOL: 10%; VOLTAGE: 16V
C130 C139 C143 C144 C146 = CAP_NP: CLASS: DISCRETE; Mfr_Name: MURATA; Mfr_Part_Number: GRM21BR71A106KE51L; TOL: 10%; VOLTAGE: 10V
C133 C136 = CAP_NP_2: Mfr_Name: MURATA; Mfr_Part_Number: GRM155R71C153KA01D; TOL: 10%; VOLTAGE: 16V
C145 C147 = CAP_NP_1: Mfr_Name: Murata; Mfr_Part_Number: GRM31CR60J226KE19L; TOL: 10%; VOLTAGE: 6.3V
C148 = CAP_NP_1: Mfr_Name: TDK CORP; Mfr_Part_Number: C1005C0G1H330G050BA; TOL: 2%; VOLTAGE: 50V
FB30 FB31 = BEAD_NFM31P: Mfr_Name: MURATA; Mfr_Part_Number: NFM31PC276B0J3; Tolerance: 20%
FB34 = FERRITE_BEAD_0402_H: Mfr_Name: Taiyo Yuden; Mfr_Part_Number: FBMH4525HM102NT
L17 L18 = IND1206: Mfr_Name: Coilcraft; Mfr_Part_Number: LPS3015-222ML; Tolerance: 20%
R148 = R: CLASS: DISCRETE; Mfr_Name: PANASONIC; Mfr_Part_Number: ERJ-2RKF4753X; TOL: 1%; Wattage: 1/16W
R150 = R: CLASS: DISCRETE; Mfr_Name: PANASONIC; Mfr_Part_Number: ERJ-2RKF9532X; TOL: 1%; Wattage: 1/16W
R151 = R: CLASS: DISCRETE; Mfr_Name: Yageo; Mfr_Part_Number: RC0402FR-07150KL; TOL: 1%; Wattage: 1/16W
R153 = R: CLASS: DISCRETE; Mfr_Name: Vishay/Dale; Mfr_Part_Number: CRCW0402182KFKED; TOL: 1%; Wattage: 1/16W
R173 = Res_0603_2.87K_H
R174 = Res_0603_3.65K
R175 = Res_0603_4.99K
R176 = Res_0603_634
SH1-SH4 = HEATSINK: Mfr_Name: LEADER TECH; Mfr_Part_Number: SL-11356_DNI; Note: DNI
TP20 = TESTPOINT_BLUE: TI_SILKTEXT: +2.5V_LDO_IN
TP21 = TESTPOINT_GRN: TI_SILKTEXT: +0.9V_DAC
TP26 = TESTPOINT_GRN: TI_SILKTEXT: +1.8V_DAC
TP28 = TESTPOINT_GRN: TI_SILKTEXT: +0.9V_DACDIG
U7 = TPS62420_SON10_1: Mfr_Name: Texas Instruments; Mfr_Part_Number: TPS62420DRCR
U9 U11 = TPS74201_QFN20: Mfr_Name: Texas Instruments; Mfr_Part_Number: TPS74201RGWR

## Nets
1.8V_CPLD: C155.2 C156.2 C162.2 C165.2 C166.2 J15.4 JP3.1(Pin1) JP5.2(Pin2) R110.2 R111.2 U1.9(VCCIO1) U1.13(VCCINT) U1.31(VCCIO1) U1.45(VCCIO1) U1.63(VCCINT)
1.8V_USB: JP5.3(Pin3) ; also on sheet 10
3.3V_CPLD: C152.2 C153.2 C154.2 C200.1 JP6.2(Pin2) R107.1 U1.59(VCCIO2) U1.80(VCCIO2) U1.94(VCCIO2) U15.5(VCC)
3.3V_USB: JP6.3(Pin3) ; also on sheet 10
+0.9V_DAC: C137.1 C138.1 C139.1 C345.1 C346.1 C347.1 C348.1 FB18.1 FB19.1 R176.1 R192.1 TP21.1(TP) U9.1(OUT4) U9.18(OUT1) U9.19(OUT2) U9.20(OUT3)
+0.9V_VDDCLK: C6.1 C7.1 C9.1 C349.1 C350.1 FB18.2 PP2.1 U2.A8(VDDCLK09_1) U2.B8(VDDCLK09_2)
+0.9V_VDDDAC: C10.1 C182.1 C183.1 C184.1 C185.1 C186.1 C187.1 C343.1 C344.1 FB19.2 PP3.1 U2.D9(VDDDAC09_1) U2.E9(VDDDAC09_2) U2.F9(VDDDAC09_3) U2.G9(VDDDAC09_4) U2.H9(VDDDAC09_5) U2.J9(VDDDAC09_6)
+0.9V_VDDDIG: C11.1 C13.1 C14.1 C146.1 C149.1 C171.1 C174.1 C175.1 C176.1 C177.1 C178.1 C179.1 C180.1 C181.1 FB30.3 PP9.1 TP28.1(TP) U2.D3(VDDDIG09_1) U2.D4(VDDDIG09_2) U2.D5(VDDDIG09_8) U2.E4(VDDDIG09_3) U2.F4(VDDDIG09_4) U2.G4(VDDDIG09_5) U2.H4(VDDDIG09_6) U2.J4(VDDDIG09_7) U2.J5(VDDDIG09_9) U2.J6(VDDDIG09_10) U2.J7(VDDDIG09_11)
+0.9V_VDDT: C3.1 C4.1 C5.1 PP1.1 R192.2 U2.F3(VDDT09_1) U2.G3(VDDT09_2)
+1.8V_DAC: C128.1 C129.1 C130.1 C353.1 C354.1 C361.1 C362.1 C365.1 C366.1 FB25.1 FB29.1 FB32.1 R174.1 R193.1 R194.1 TP26.1(TP) U11.1(OUT4) U11.18(OUT1) U11.19(OUT2) U11.20(OUT3)
+1.8V_VDDAPLL: C17.1 C25.1 C26.1 C351.1 C352.1 FB25.2 PP5.1 U2.B9(VDDAPLL18_1) U2.B10(VDDAPLL18_2)
+1.8V_VDDAREF: C20.1 C31.1 C32.1 C359.1 C360.1 FB32.2 PP10.1 U2.C10(VDDAREF18_1) U2.K10(VDDAREF18_2)
+1.8V_VDDIO: C15.1 C23.1 C24.1 JP1.1(Pin1) JP4.1(Pin1) JP5.1(Pin1) PP4.1 R63.1 R193.2 U2.K6(VDDIO18_1) U2.K7(VDDIO18_2)
+1.8V_VDDR: C21.1 C33.1 C34.1 C363.1 C364.1 FB29.2 PP11.1 U2.F2(VDDR18_1) U2.G2(VDDR18_2)
+1.8V_VDDS: C18.1 C27.1 C28.1 PP7.1 R191.1 R194.2 U2.C6(VDDS18_1) U2.C7(VDDS18_2)
+2.5V_LDO_IN: C119.1 C126.1 C135.1 C144.1 FB31.3 TP20.1(TP) U9.5(IN1) U9.6(IN2) U9.7(IN3) U9.8(IN4) U9.11(EN) U11.5(IN1) U11.6(IN2) U11.7(IN3) U11.8(IN4) U11.11(EN)
+3.3V_DAC: C127.1 C134.1 C357.1 C358.1 FB33.1 U9.10(BIAS) U11.10(BIAS) ; also on sheet 9
+3.3V_VDDADAC: C22.1 C169.1 C170.1 C172.1 C173.1 C355.1 C356.1 FB33.2 PP6.1 U2.D10(VDDADAC33_1) U2.E10(VDDADAC33_2) U2.H10(VDDADAC33_3) U2.J10(VDDADAC33_4)
+3.3VCLK: C69.1 C70.1 C71.1 C72.1 C73.1 FB2.1 FB3.1 FB6.1 FB7.1 FB8.1 FB9.1 FB10.1 JP2.2 JP6.1(Pin1) R73.1 R78.1 SJP1.1(Pin1) ; also on sheet 9 10
+5.0V: FB34.1 ; also on sheet 8 9
GND: C3.2 C4.2 C5.2 C6.2 C7.2 C9.2 C10.2 C11.2 C13.2 C14.2 C15.2 C17.2 C18.2 C20.2 C21.2 C22.2 C23.2 C24.2 C25.2 C26.2 C27.2 C28.2 C31.2 C32.2 C33.2 C34.2 C50.2 C53.2 C57.2 C58.2 C59.2 C60.2 C63.2 C64.2 C65.2 C66.2 C69.2 C70.2 C71.2 C72.2 C73.2 C78.1 C81.1 C84.1 C85.1 C87.2 C88.2 C90.1 C117.2 C119.2 C120.1 C121.1 C126.2 C127.2 C128.2 C129.2 C130.2 C133.2 C134.2 C135.2 C136.2 C137.2 C138.2 C139.2 C143.2 C144.2 C145.2 C146.2 C147.2 C149.2 C150.2 C152.1 C153.1 C154.1 C155.1 C156.1 C162.1 C165.1 C166.1 C167.2 C168.2 C169.2 C170.2 C171.2 C172.2 C173.2 C174.2 C175.2 C176.2 C177.2 C178.2 C179.2 C180.2 C181.2 C182.2 C183.2 C184.2 C185.2 C186.2 C187.2 C199.2 C200.2 C207.1 C343.2 C344.2 C345.2 C346.2 C347.2 C348.2 C349.2 C350.2 C351.2 C352.2 C353.2 C354.2 C355.2 C356.2 C357.2 C358.2 C359.2 C360.2 C361.2 C362.2 C363.2 C364.2 C365.2 C366.2 D4.2(CATHODE) D5.2(CATHODE) D6.2(CATHODE) D7.2(CATHODE) FB30.2 FB31.2 GP1.1 GP2.1 GP3.1 GP4.1 GP5.1 GP6.1 GP7.1 GP8.1 J1.2(SHIELD1) J2.2(GND) J2.3(GND) J2.4(GND) J2.5(GND) J3.2(SHIELD1) J4.2(GND) J4.3(GND) J4.4(GND) J4.5(GND) J5.2(SHIELD1) J6.2(GND) J6.3(GND) J6.4(GND) J6.5(GND) J7.2(SHIELD1) J8.2(GND) J8.3(GND) J8.4(GND) J8.5(GND) J9.2(GND) J9.3(GND) J9.4(GND) J9.5(GND) J10.2(GND) J10.3(GND) J10.4(GND) J10.5(GND) J11.2(GND) J11.3(GND) J11.4(GND) J11.5(GND) J12.2(GND) J12.3(GND) J12.4(GND) J12.5(GND) J13.2(SHIELD1) J15.2 J15.10 J17.2(GND) J17.3(GND) J17.4(GND) J17.5(GND) J18.2(SHIELD1) J19.2(SHIELD1) J20.2(SHIELD1) J21.2 J21.4 J21.6 J21.8 J22.2(SHIELD1) J24.1 J24.3 J24.5 J24.7 J24.9 J24.11 J24.13 J24.15 J24.17 J24.19 J25.1 J25.3 J25.5 J25.7 J25.9 J25.11 J25.13 J25.15 J25.17 J25.19 JP1.3(Pin3) JP3.3(Pin3) JP4.3(Pin3) R3.1 R6.1 R8.2 R10.1 R11.2 R12.1 R13.1 R15.1 R19.1 R20.1 R22.2 R23.2 R24.2 R26.2 R28.2 R29.2 R31.2 R32.1 R34.2 R35.2 R36.2 R37.2 R39.2 R40.2 R41.1 R44.2 R45.1 R48.2 R49.2 R57.2 R65.2 R66.2 R67.2 R68.2 R69.2 R70.2 R71.2 R72.1 R74.2 R75.2 R76.2 R77.2 R79.2 R80.2 R83.2 R84.2 R87.2 R89.2 R98.2 R99.2 R100.2 R102.1 R103.1 R104.2 R112.1 R114.2 R115.1 R116.1 R117.1 R118.2 R122.2 R123.2 R124.2 R125.2 R129.1 R130.1 R131.2 R132.1 R134.2 R136.1 R151.1 R153.1 R173.1 R175.2 R179.2 R180.2 R181.2 R182.2 R183.2 R184.1 R195.1 R196.2 R197.1 R198.2 R199.1 R200.2 R201.1 R202.2 SJP1.3(Pin3) SW1.1 SW1.2 SW2.1 SW2.2 TP7.1(TP) TP8.1(TP) U1.1(GND) U1.10(GND) U1.11(GND) U1.32(GND) U1.46(GND) U1.60(GND) U1.65(GND) U1.79(GND) U1.93(GND) U2.A4(GND38) U2.A5(GND32) U2.A11(GND5) U2.A12(GND1) U2.B2(GND44) U2.B3(GND41) U2.B4(GND39) U2.B5(GND33) U2.B11(GND6) U2.C2(GND45) U2.C3(GND42) U2.C8(GND17) U2.C11(GND7) U2.D2(GND46) U2.D8(GND18) U2.D11(GND8) U2.E2(GND47) U2.E5(GND34) U2.E6(GND28) U2.E7(GND24) U2.E8(GND19) U2.E11(GND9) U2.F5(GND35) U2.F6(GND29) U2.F7(GND25) U2.F8(GND20) U2.F11(GND10) U2.F12(GND2) U2.G5(GND36) U2.G6(GND30) U2.G7(GND26) U2.G8(GND21) U2.G11(GND11) U2.G12(GND3) U2.H2(GND48) U2.H5(GND37) U2.H6(GND31) U2.H7(GND27) U2.H8(GND22) U2.H11(GND12) U2.J2(GND49) U2.J8(GND23) U2.J11(GND13) U2.K2(GND50) U2.K11(GND14) U2.L2(GND51) U2.L3(GND43) U2.L11(GND15) U2.M4(GND40) U2.M11(GND16) U2.M12(GND4) U5.65(DAP) U7.8(GND) U7.11(THERMPAD) U9.2(NC1) U9.3(NC2) U9.4(NC3) U9.12(GND) U9.13(NC4) U9.14(NC5) U9.17(NC6) U9.21(PWRPAD) U11.2(NC1) U11.3(NC2) U11.4(NC3) U11.12(GND) U11.13(NC4) U11.14(NC5) U11.17(NC6) U11.21(PWRPAD) U15.3(GND) Y1.3(GND) ; also on sheet 8 9 10
ALARM: TP24.1(TP) U2.L8(ALARM)
AMUX0: TP2.1(TP) U2.H3(AMUX0)
AMUX1: TP1.1(TP) U2.E3(AMUX1)
AN_OUT: R12.2 R14.1 T2.4(Primary)
ANOUT: J4.1(CENTER) R14.2
AP_OUT: R2.2 R15.2 T2.6(Primary_Dot)
APOUT: J2.1(CENTER) R2.1
ATEST: TP23.1(TP) U2.K9(ATEST)
BN_OUT: R22.1 R27.1 T4.6(Primary_Dot)
BNOUT: J8.1(CENTER) R27.2
BP_OUT: R17.1 R19.2 T4.4(Primary)
BPOUT: J6.1(CENTER) R17.2
CAR_SYSREFM: R108.2 ; also on sheet 8
CAR_SYSREFP: R109.2 ; also on sheet 8
CLK_IN: C122.1 R100.1 R177.2
CLK_LAO_0M: C89.1 ; also on sheet 8
CLK_LAO_0P: C86.1 ; also on sheet 8
CLKIN: J17.1(CENTER) R177.1 R185.1
CLKIN1N: C78.2 C198.2 U5.35(CLKIN1n/FBCLKINn/FINn)
CLKIN1P: C122.2 U5.34(CLKIN1p/FBCLKINp/FINp)
CLKLA_0N: C89.2 R80.1 U5.63(DCLKOUT12n)
CLKLA_0P: C86.2 R79.1 U5.62(DCLKOUT12p)
CLKN: C340.2 R18.2 R182.1
CLKOUT0_N: C83.2 J18.1(CENTER)
CLKOUT0_P: C79.2 J13.1(CENTER)
CLKOUT1_N: C93.2 J20.1(CENTER)
CLKOUT1_P: C91.2 J19.1(CENTER)
CLKP: C341.2 R16.2 R181.1
CMOS_SYNC_AB: J21.1 U2.L6(NC1) ; also on sheet 8
CMOS_SYNC_CD: J21.3 U2.L7(NC2) ; also on sheet 8
CN_OUT: R41.2 R42.1 T6.4(Primary)
CNOUT: J10.1(CENTER) R42.2
CP1: C60.1 C61.1 C120.2 U5.32(CPOUT1) Y1.1(VC)
CP2: C62.1 C63.1 U5.46(CPOUT2)
CP_OUT: R30.1 R102.2 T6.6(Primary_Dot)
CPLD_SYNC: SJP2.3(Pin3) U1.82(IO_2_82/DIFFIO_T8P)
CPOUT: J9.1(CENTER) R30.2
DAC_RESET: C168.1 R63.2 SW1.3 SW1.4 U1.37(IO_1_37/DIFFIO_B5N) U2.K8(RESETB)
DAC_SCLK: U1.33(IO_1_33/DIFFIO_B3N) U2.L9(SCLK)
DAC_SDENB: U1.34(IO_1_34/DIFFIO_B4P) U2.M9(SDENB)
DAC_SDIO: U1.35(IO_1_35/DIFFIO_B4N) U2.L10(SDIO)
DAC_SDO: U1.36(IO_1_36/DIFFIO_B5P) U2.M10(SDO)
DAC_TCLK: U1.40(IO_1_40/DIFFIO_B6N) U2.K4(TCLK)
DAC_TDI: U1.41(IO_1_41/DIFFIO_B7P) U2.L5(TDI)
DAC_TDO: U1.42(IO_1_42/DIFFIO_B7N) U2.M5(TDO)
DAC_TMS: U1.43(IO_1_43/DEV_OE/DIFFIO_B8P) U2.L4(TMS)
DAC_TRSTB: U1.44(IO_1_44/DEV_CLRN/DIFFIO_B5N) U2.J3(TRSTB)
DCLK_N: C16.2 R13.2 R18.1 R188.2 U2.A9(DACCLKN)
DCLK_P: C12.2 R16.1 R112.2 R187.2 U2.A10(DACCLKP)
DCLKOUT0N: C83.1 R76.1 U5.28(DCLKOUT6n)
DCLKOUT0P: C79.1 R75.1 U5.27(DCLKOUT6p)
DCLKOUT2N: C340.1 R179.1 U5.15(DCLKOUT2p)
DCLKOUT2P: C341.1 R180.1 U5.16(DCLKOUT2n)
DCLKOUT8N: C74.1 R122.1 U5.52(DCLKOUT8n)
DCLKOUT8P: C75.1 R123.1 U5.51(DCLKOUT8p)
DN_OUT: R50.1 R103.2 T8.6(Primary_Dot)
DNOUT: J11.1(CENTER) R50.2
DP0_C2M_N_A: C190.1 ; also on sheet 8
DP0_C2M_P_A: C191.1 ; also on sheet 8
DP1_C2M_N_A: C193.1 ; also on sheet 8
DP1_C2M_P_A: C192.1 ; also on sheet 8
DP2_C2M_N_A: C195.1 ; also on sheet 8
DP2_C2M_P_A: C194.1 ; also on sheet 8
DP3_C2M_N_A: C197.1 ; also on sheet 8
DP3_C2M_P_A: C196.1 ; also on sheet 8
DP4_C2M_N_A: C189.1 ; also on sheet 8
DP4_C2M_P_A: C188.1 ; also on sheet 8
DP5_C2M_N_A: C40.1 ; also on sheet 8
DP5_C2M_P_A: C39.1 ; also on sheet 8
DP6_C2M_N_A: C38.1 ; also on sheet 8
DP6_C2M_P_A: C37.1 ; also on sheet 8
DP7_C2M_N_A: C36.1 ; also on sheet 8
DP7_C2M_P_A: C35.1 ; also on sheet 8
DP_OUT: R43.1 R44.1 T8.4(Primary)
DPOUT: J12.1(CENTER) R43.2
EXTIO: C167.1 TP14.1(TP) U2.F10(EXTIO)
FMC_B5: U1.7(IO_1_7/DIFFIO_L3N) ; also on sheet 8
FMC_B6: U1.8(IO_1) ; also on sheet 8
FMC_DACCLK_N: R188.1 ; also on sheet 8
FMC_DACCLK_P: R187.1 ; also on sheet 8
FMC_DIR_CONTROL: U1.15(IO_1) ; also on sheet 8
FMC_SCLK: U1.2(IO_1_2/DIFFIO_L1P) ; also on sheet 8
FMC_SDIO: U1.3(IO_1_3/DIFFIO_L1N) ; also on sheet 8
FMC_SDO: U1.4(IO_1_4/DIFFIO_L2P) ; also on sheet 8
FMC_SEN_DAC: U1.5(IO_1_5/DIFFIO_L2N) ; also on sheet 8
FMC_SEN_LMK: U1.6(IO_1_6/DIFFIO_L3P) ; also on sheet 8
FMC_SYSREF_N: R189.1 ; also on sheet 8
FMC_SYSREF_P: R190.1 ; also on sheet 8
FPGA_CLK1N: C74.2 ; also on sheet 8
FPGA_CLK1P: C75.2 ; also on sheet 8
FPGA_CLK2N: C95.2 ; also on sheet 8
FPGA_CLK2P: C94.2 ; also on sheet 8
FTDI_A5: U1.70(IO_2) ; also on sheet 10
FTDI_A6: U1.69(IO_2_69/DIFFIO_R3P) ; also on sheet 10
FTDI_A7: U1.68(IO_2_68/DIFFIO_R3N) ; also on sheet 10
FTDI_DAC_SDIO_READ: U1.54(IO_2_54/DIFFIO_R7P) ; also on sheet 10
FTDI_DIR_CONTROL: U1.52(IO_2) ; also on sheet 10
FTDI_LMK_SDIO_READ: U1.53(IO_2_53/DIFFIO_R7N) ; also on sheet 10
FTDI_SCLK: U1.61(IO_2) ; also on sheet 10
FTDI_SDIO: U1.58(IO_2_58/DIFFIO_R5P) ; also on sheet 10
FTDI_SDO: U1.57(IO_2_57/DIFFIO_R5N) ; also on sheet 10
FTDI_SEN_DAC: U1.56(IO_2_56/DIFFIO_R6P) ; also on sheet 10
FTDI_SEN_LMK: U1.55(IO_2_55/DIFFIO_R6N) ; also on sheet 10
FTDI_TCK: U1.75(IO_2_75/DIFFIO_T10N) ; also on sheet 10
FTDI_TDI: U1.74(IO_2_74/DIFFIO_R1P) ; also on sheet 10
FTDI_TDO: U1.73(IO_2_73/DIFFIO_R1N) ; also on sheet 10
FTDI_TMS: U1.72(IO_2_72/DIFFIO_R2P) ; also on sheet 10
FTDI_TRSTB: U1.71(IO_2_71/DIFFIO_R2N) ; also on sheet 10
GTX_CLKM: C68.2 ; also on sheet 8
GTX_CLKP: C67.2 ; also on sheet 8
GTXCLKM: C68.1 R68.1 U5.2(DCLKOUT0n)
GTXCLKP: C67.1 R67.1 U5.1(DCLKOUT0p)
IFORCE: TP15.1(TP) U2.C5(IFORCE)
IOUTAN: R8.1 R9.1 R39.1 R117.2 U2.C12(IOUTAN)
IOUTAP: R3.2 R5.1 R36.1 R114.1 U2.B12(IOUTAP)
IOUTBN: R23.1 R25.1 R35.1 R129.2 U2.D12(IOUTBN)
IOUTBP: R20.2 R21.1 R34.1 R118.1 U2.E12(IOUTBP)
IOUTCN: R31.1 R37.1 R38.1 R131.1 U2.J12(IOUTCN)
IOUTCP: R29.1 R32.2 R33.1 R130.2 U2.H12(IOUTCP)
IOUTDN: R28.1 R47.1 R48.1 R134.1 U2.K12(IOUTDN)
IOUTDP: R26.1 R45.2 R46.1 R132.2 U2.L12(IOUTDP)
J1_P: C12.1 J1.1(CENTER)
J3_N: C16.1 J3.1(CENTER)
J5_P: C1.1 J5.1(CENTER)
J7_N: C8.1 J7.1(CENTER)
LMK_CS: U1.78(IO_2_78/DIFFIO_T9P) U5.18(\\~{CS})
LMK_SCK: U1.77(IO_2_77/DIFFIO_T9N) U5.19(SCK)
LMK_SDIO: U1.76(IO_2_76/DIFFIO_T10P) U5.20(SDIO)
LMK_SDO: R113.2 U5.5(RESET)
LMK_SYNC: SJP2.2(Pin2) U5.6(SYNC)
LPF: R133.2 U2.C9(LPF)
OSCIN_N: C82.2 U5.44(OSCINn)
OSCIN_P: C92.2 C121.2 U5.43(OSCINp)
OUT_AN: T1.1(primary) T2.3(Secondary)
OUT_AP: T1.3(primary_dot) T2.1(Secondary_Dot)
OUT_BN: T3.3(primary_dot) T4.1(Secondary_Dot)
OUT_BP: T3.1(primary) T4.3(Secondary)
OUT_CN: T5.1(primary) T6.3(Secondary)
OUT_CP: T5.3(primary_dot) T6.1(Secondary_Dot)
OUT_DN: T7.3(primary_dot) T8.1(Secondary_Dot)
OUT_DP: T7.1(primary) T8.3(Secondary)
RX0N: C190.2 U2.M2(RX3N)
RX0P: C191.2 U2.M3(RX3P)
RX1N: C193.2 U2.M1(RX2N)
RX1P: C192.2 U2.L1(RX2P)
RX2N: C195.2 U2.J1(RX1N)
RX2P: C194.2 U2.K1(RX1P)
RX3N: C197.2 U2.H1(RX0N)
RX3P: C196.2 U2.G1(RX0P)
RX4N: C189.2 U2.D1(RX5N)
RX4P: C188.2 U2.C1(RX5P)
RX5N: C40.2 U2.A2(RX7N)
RX5P: C39.2 U2.A3(RX7P)
RX6N: C38.2 U2.A1(RX6N)
RX6P: C37.2 U2.B1(RX6P)
RX7N: C36.2 U2.E1(RX4N)
RX7P: C35.2 U2.F1(RX4P)
SDCLKOUT1N: C93.1 R84.1 U5.30(SDCLKOUT7n)
SDCLKOUT1P: C91.1 R83.1 U5.29(SDCLKOUT7p)
SDCLKOUT3N: R89.1 R106.1 U5.13(SDCLKOUT3p)
SDCLKOUT3P: R98.1 R105.1 U5.14(SDCLKOUT3n)
SDCLKOUT9N: C95.1 R125.1 U5.50(SDCLKOUT9n)
SDCLKOUT9P: C94.1 R124.1 U5.49(SDCLKOUT9p)
SLEEP: JP4.2(Pin2) U2.M8(SLEEP)
SYNC: J22.1(CENTER) SJP2.1(Pin1)
SYNCN: U2.B6(SYNCBN) ; also on sheet 8
SYNCP: U2.B7(SYNCBP) ; also on sheet 8
SYS_N: C8.2 R6.2 R7.1 R189.2 U2.A6(SYSREFN)
SYS_P: C1.2 R4.1 R10.2 R190.2 U2.A7(SYSREFP)
SYSREF_M: R70.1 R108.1 U5.4(SDCLKOUT1n)
SYSREF_P: R69.1 R109.1 U5.3(SDCLKOUT1p)
SYSREFN: R7.2 R106.2 R116.2
SYSREFP: R4.2 R105.2 R115.2
TCK: J15.1 R57.1 U1.24(TCK)
TDI: J15.9 R110.1 U1.23(TDI)
TDO: J15.3 U1.25(TDO)
TESTMODE: TP25.1(TP) U2.K3(TESTMODE)
TMS: J15.5 R111.1 U1.22(TMS)
TXENABLE: JP1.2(Pin2) U2.K5(TXENABLE)
VSENSE: TP16.1(TP) U2.C4(VSENSE)
N16905345: C53.1 R62.1 R133.1
N16905395: C50.1 R62.2
N16906481: R135.1 U2.G10(RBIAS)
N16906487: R135.2 R136.2
N16918679: C81.2 C84.2 C85.2 C90.2 FB17.1 Y1.6(VDD)
N16918713: R78.2 R87.1 R88.1 Y1.5(OUT_P)
N16918734: R73.2 R74.1 R138.1 Y1.4(OUT_N)
N16918766: FB17.2 JP2.1
N16918796: C80.1 R138.2
N16918798: C80.2 C82.1 R77.1
N16918863: C92.1 C206.2 R99.1 R186.2
N16918987: SJP1.2(Pin2) Y1.2(NC)
N16957588: R173.2 R174.2 U11.16(FB/SNS)
N16974113: R113.1 U1.81(IO_2_81/DIFFIO_T8N)
N16976956: JP3.2(Pin2) U1.51(IO_1_51/DIFFIO_B10N)
N16991585: C117.1 C143.1 C150.1 C207.2 FB34.2 U7.2(MODE/DATA) U7.3(VIN) U7.7(EN1) U7.9(EN2)
N16991666: L17.1 U7.6(SW1)
N16991670: R148.1 R151.2 U7.5(DEF_1)
N16991672: C148.2 R150.1 R153.2 U7.1(ADJ2)
N16992144: C145.1 C148.1 FB30.1 L18.2 R150.2
N16992172: C147.1 FB31.1 L17.2 R148.2 U7.4(FB1)
N16994752: L18.1 U7.10(SW2)
N17000669: R175.1 R176.2 U9.16(FB/SNS)
N17014647: C64.1 C65.1 C66.1 FB3.2 FB4.1 FB5.1 U5.42(VCC8_OSCin) U5.47(VCC10_PLL2)
N17015106: C57.1 C58.1 C59.1 FB2.2 U5.10(VCC1_VCO) U5.33(VCC5_DIG) U5.36(VCC6_PLL1)
N17015690: FB4.2 U5.45(VCC9_CP2)
N17015695: FB5.2 U5.39(VCC7_OSCout)
N17015811: FB6.2 U5.17(VCC2_GC1)
N17015820: FB8.2 U5.21(VCC3_SYSREF)
N17015829: FB7.2 U5.26(VCC4_CG2)
N17015838: FB9.2 U5.53(VCC11_CG3)
N17015851: FB10.2 U5.64(VCC12_CG0)
N17045898: C206.1 R88.2
N17071256: J21.5 U2.M7(NC4)
N17071268: J21.7 U2.M6(NC3)
N17135362: C198.1 R104.1
N17199056: C199.1 R107.2 SW2.3 SW2.4 U15.2(A)
N17199129: U1.88(IO_2_88/DIFFIO_T5P) U15.4(Y)
N17206708: J24.2 U1.16(IO_1_16/DIFFIO_L4P)
N17206717: J24.4 U1.17(IO_1_17/DIFFIO_L4N)
N17206727: J24.6 U1.18(IO_1_18/DIFFIO_L5P)
N17206729: J24.8 U1.19(IO_1_19/DIFFIO_L5N)
N17206761: J24.10 U1.20(IO_1_20/DIFFIO_L6P)
N17206763: J24.12 U1.21(IO_1_21/DIFFIO_L6N)
N17206775: J24.14 U1.26(IO_1_26/DIFFIO_B1P)
N17206777: J24.16 U1.27(IO_1_27/DIFFIO_B1N)
N17206789: J24.18 U1.28(IO_1_28/DIFFIO_B2P)
N17206791: J24.20 U1.29(IO_1_29/DIFFIO_B2N)
N17207204: J25.2 U1.89(IO_2_89/DIFFIO_T4N)
N17207206: J25.4 U1.90(IO_2_90/DIFFIO_T4P)
N17207236: J25.6 U1.91(IO_2)
N17207238: J25.8 U1.92(IO_2_92/DIFFIO_T3N)
N17207240: J25.10 U1.95(IO_2_95/DIFFIO_T3P)
N17207242: J25.12 U1.96(IO_2_96/DIFFIO_T2N)
N17207244: J25.14 U1.97(IO_2_97/DIFFIO_T2P)
N17207246: J25.16 U1.98(IO_2_98/DIFFIO_T1N)
N17207248: J25.18 U1.99(IO_2_99/DIFFIO_T1P)
N17207250: J25.20 U1.100(IO_2)
N17292342: R71.1 T1.5(secondary_ct)
N17293168: R184.2 T3.5(secondary_ct)
N17293265: R72.2 T7.5(secondary_ct)
N17301088: C133.1 U11.15(SS)
N17301089: C136.1 U9.15(SS)
N17316333: R185.2 R186.1
N17352995: R191.2 U2.D6(VQPS18_1) U2.D7(VQPS18_2)
N17361393: C62.2 R65.1
N17361394: C61.2 R66.1
N17375290: R11.1 T2.2(unused)
N17375633: R9.2 R196.1 T1.6(secondary)
N17385404: R24.1 T4.2(unused)
N17385560: R25.2 R198.1 T3.4(secondary_dot)
N17385723: R40.1 T6.2(unused)
N17386229: R183.1 T5.5(secondary_ct)
N17386239: R38.2 R200.1 T5.6(secondary)
N17386557: R49.1 T8.2(unused)
N17386789: R47.2 R202.1 T7.4(secondary_dot)
N17392271: R5.2 R195.2 T1.4(secondary_dot)
N17393143: R21.2 R197.2 T3.6(secondary)
N17394079: R33.2 R199.2 T5.4(secondary_dot)
N17395163: R46.2 R201.2 T7.6(secondary)
N18138734: D6.1(ANODE) R85.1
N18138778: D5.1(ANODE) R82.1
N18138841: D7.1(ANODE) R86.1
N18138859: R86.2 U5.48(STATUS_LD2)
N18139187: R85.2 U5.31(STATUS_LD1)
N18582117: C88.1 U5.12(LDObyp2)
N18582124: C87.1 U5.11(LDObyp1)
N18582340: D4.1(ANODE) R81.1
N18582465: R82.2 U5.59(CLKin_SEL1)
N18582474: R81.2 U5.58(CLKin_SEL0)

Not connected (* = marked no-connect by the designer): J15 6* 7* 8*; T1 2(primary_ct)*; T3 2(primary_ct)*; T5 2(primary_ct)*; T7 2(primary_ct)*; U1 12(IO_1_12/CLK0) 14(IO_1_14/CLK1) 30(IO_1_30/DIFFIO_B3P) 38(IO_1) 39(IO_1_39/DIFFIO_B6P) 47(IO_1_47/DIFFIO_B9P) 48(IO_1_48/DIFFIO_B9N) 49(IO_1) 50(IO_1_50/DIFFIO_B10P) 62(IO_2_62/CLK2) 64(IO_2_64/CLK3) 66(IO_2_66/DIFFIO_R4N) 67(IO_2_67/DIFFIO_R4P) 83(IO_2_83/DIFFIO_T7N) 84(IO_2_84/DIFFIO_T7P) 85(IO_2_85/DIFFIO_T6N) 86(IO_2_86/DIFFIO_T6P) 87(IO_2_87/DIFFIO_T5N); U5 22(SDCLKOUT5p)* 23(SDCLKOUT5n)* 24(DCLKOUT4p)* 25(DCLKOUT4n)* 37(CLKIN0p)* 38(CLKIN0n)* 40(OSCOUTp)* 41(OSCOUTn)* 54(DCLKOUT10p)* 55(DCLKOUT10n)* 56(SDCLKOUT11p)* 57(SDCLKOUT11n)* 60(SDCLKOUT13p)* 61(SDCLKOUT13n)*; U9 9(PG)*; U11 9(PG)*; U15 1(NC)*

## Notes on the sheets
sheet 1
- DAC
- CLOCK INPUT
- DACCLK
- DAC3XJ8X
- LMK04828
- SYSREF
- PAGES 5, 6
- PAGE 4
- JESD204B
- INTERFACE
- PAGE 7
- POWER
- POWER
- TPS2400
- TPS7A8001
- TPS7A4700
- TPS74201
- PAGE 9
- PAGE 10
- USB PORT
- CPLD
- TLV70233
- SN74AUP1T14
- PAGE 8
- PAGE 3
sheet 2
- DCLK* AND SDCLK* MUST BE
- FPGA_CLK1 & FPGA_CLK2* MUST BE
- MATCHED LENGTH TO EACH OTHER.
- MATCHED LENGTH TO EACH OTHER.
- LEADER TECH RF SHIELD P/N SL-11356
- 12500 TI Boulevard. Dallas, Texas 75243
sheet 4
- 100 OHM DIFFERENTIAL - TYPICAL
- 50 OHM
- PLACE NEAR IC
- 50 OHM
- PLACE NEAR
- TRANSFORMER
- 50 OHM
- PLACE NEAR IC
- 50 OHM
- PLACE NEAR
- TRANSFORMER
- 50 OHM
- PLACE NEAR IC
- 50 OHM
- PLACE NEAR
- TRANSFORMER
- 50 OHM
- PLACE NEAR IC
- NOTES:
- 50 OHM
- 1)  DNI = DO NOT INSTALL
- PLACE NEAR
- TRANSFORMER
sheet 5
- FMC
- USB
- CPLD
sheet 6
- CLK* AND SYSREF* MUST BE
- MATCHED LENGTH TO EACH OTHER.
- GTX* AND CAR* MUST BE
- MATCHED LENGTH TO EACH OTHER.
- CLK* AND SYSREF* MUST BE
- MATCHED LENGTH TO EACH OTHER.
- C122 & R100 PLACE CLOSE TO LMK
- PLACE C120 CLOSE TO Y1
- DCLK* AND SDCLK* MUST BE
- MATCHED LENGTH TO EACH OTHER.
- C92 & C121 SHARED PAD
- C92, C121 & R99 PLACE CLOSE TO LMK
- DCLK* AND SDCLK* MUST BE
- MATCHED LENGTH TO EACH OTHER.
- C82 & R77 PLACE CLOSE TO LMK
- 12500 TI Boulevard. Dallas, Texas 75243
sheet 7
- Shared pad.
- Place as close to the DAC as possible.
- Shared pad.
- Shared pad.
- Shared pad.
- IOUTFS = 64 EXTIO 0.90V / RBIAS
- 30mA: 1.92K
- 20mA WITH COURSE DAC = 10:1980K = 1.96K +/- 20
